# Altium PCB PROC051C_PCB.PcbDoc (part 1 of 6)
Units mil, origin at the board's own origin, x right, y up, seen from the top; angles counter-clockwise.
Board outline 3304.03 x 2647.77 mil, 6 copper layers (TOP, L2, L3, L4, L5, BOTTOM), stack 55.54 mil thick; 370 components, 273 nets, 1273 pads, 1381 vias.
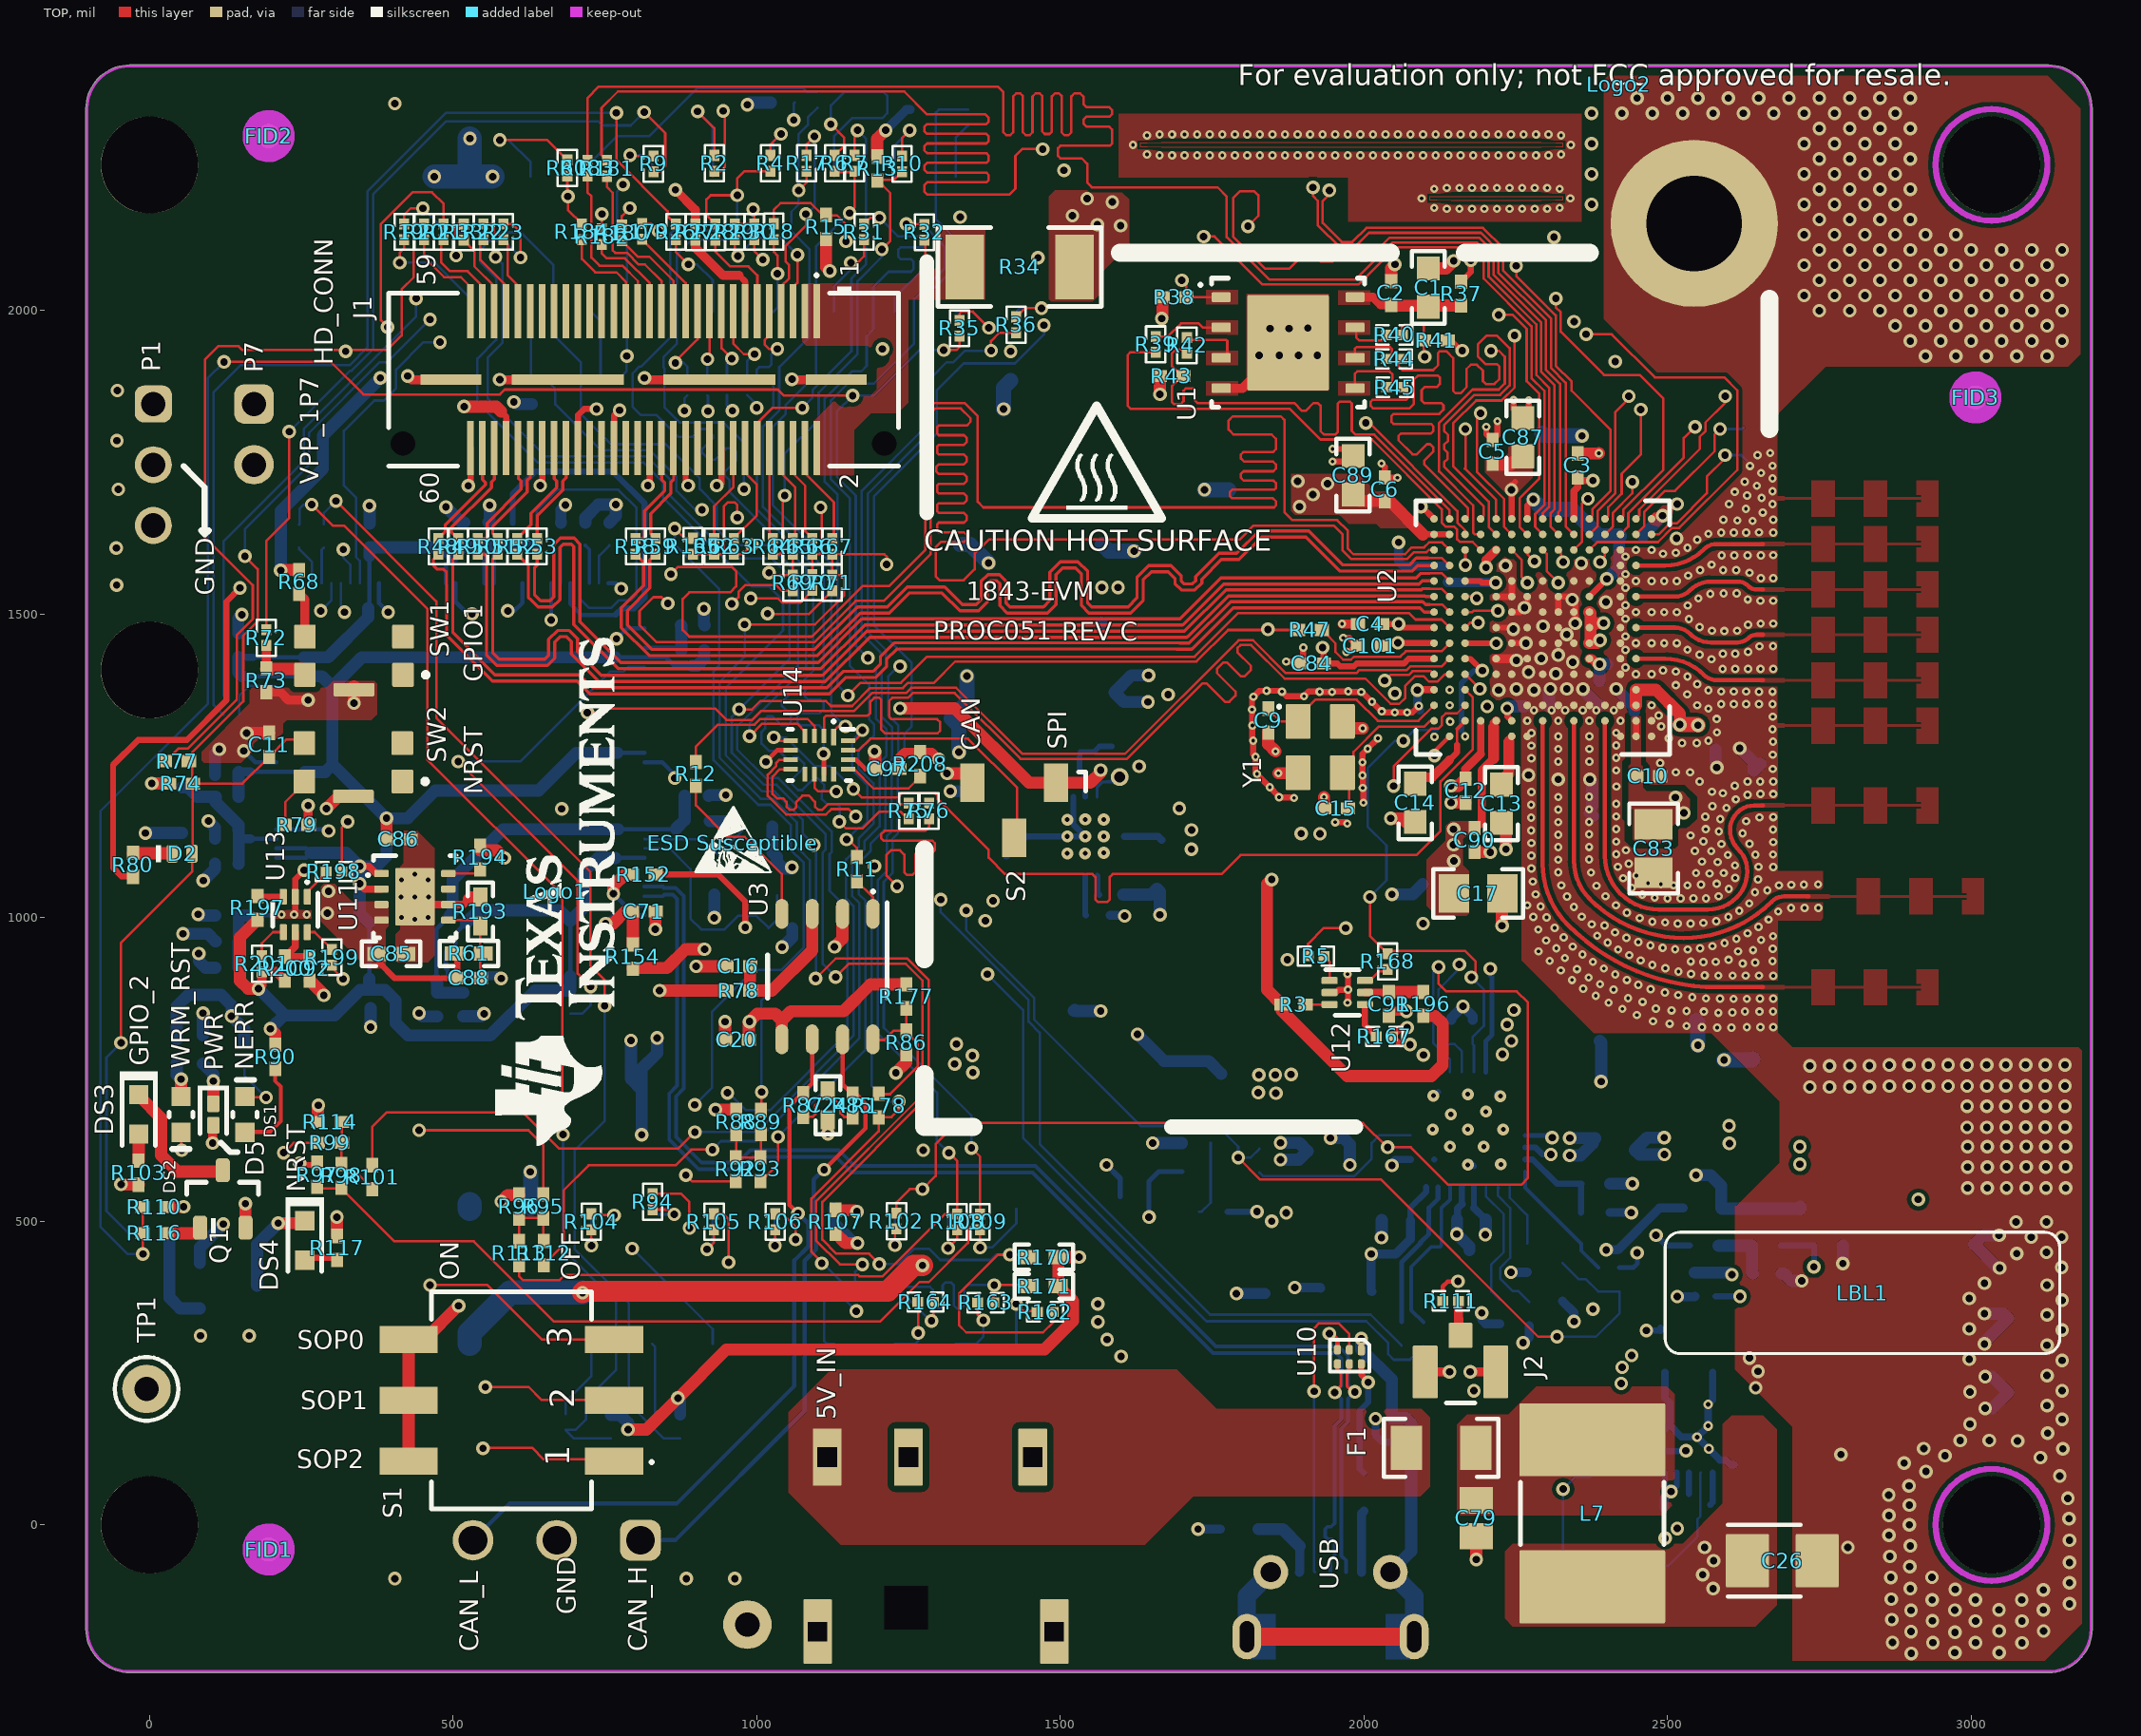
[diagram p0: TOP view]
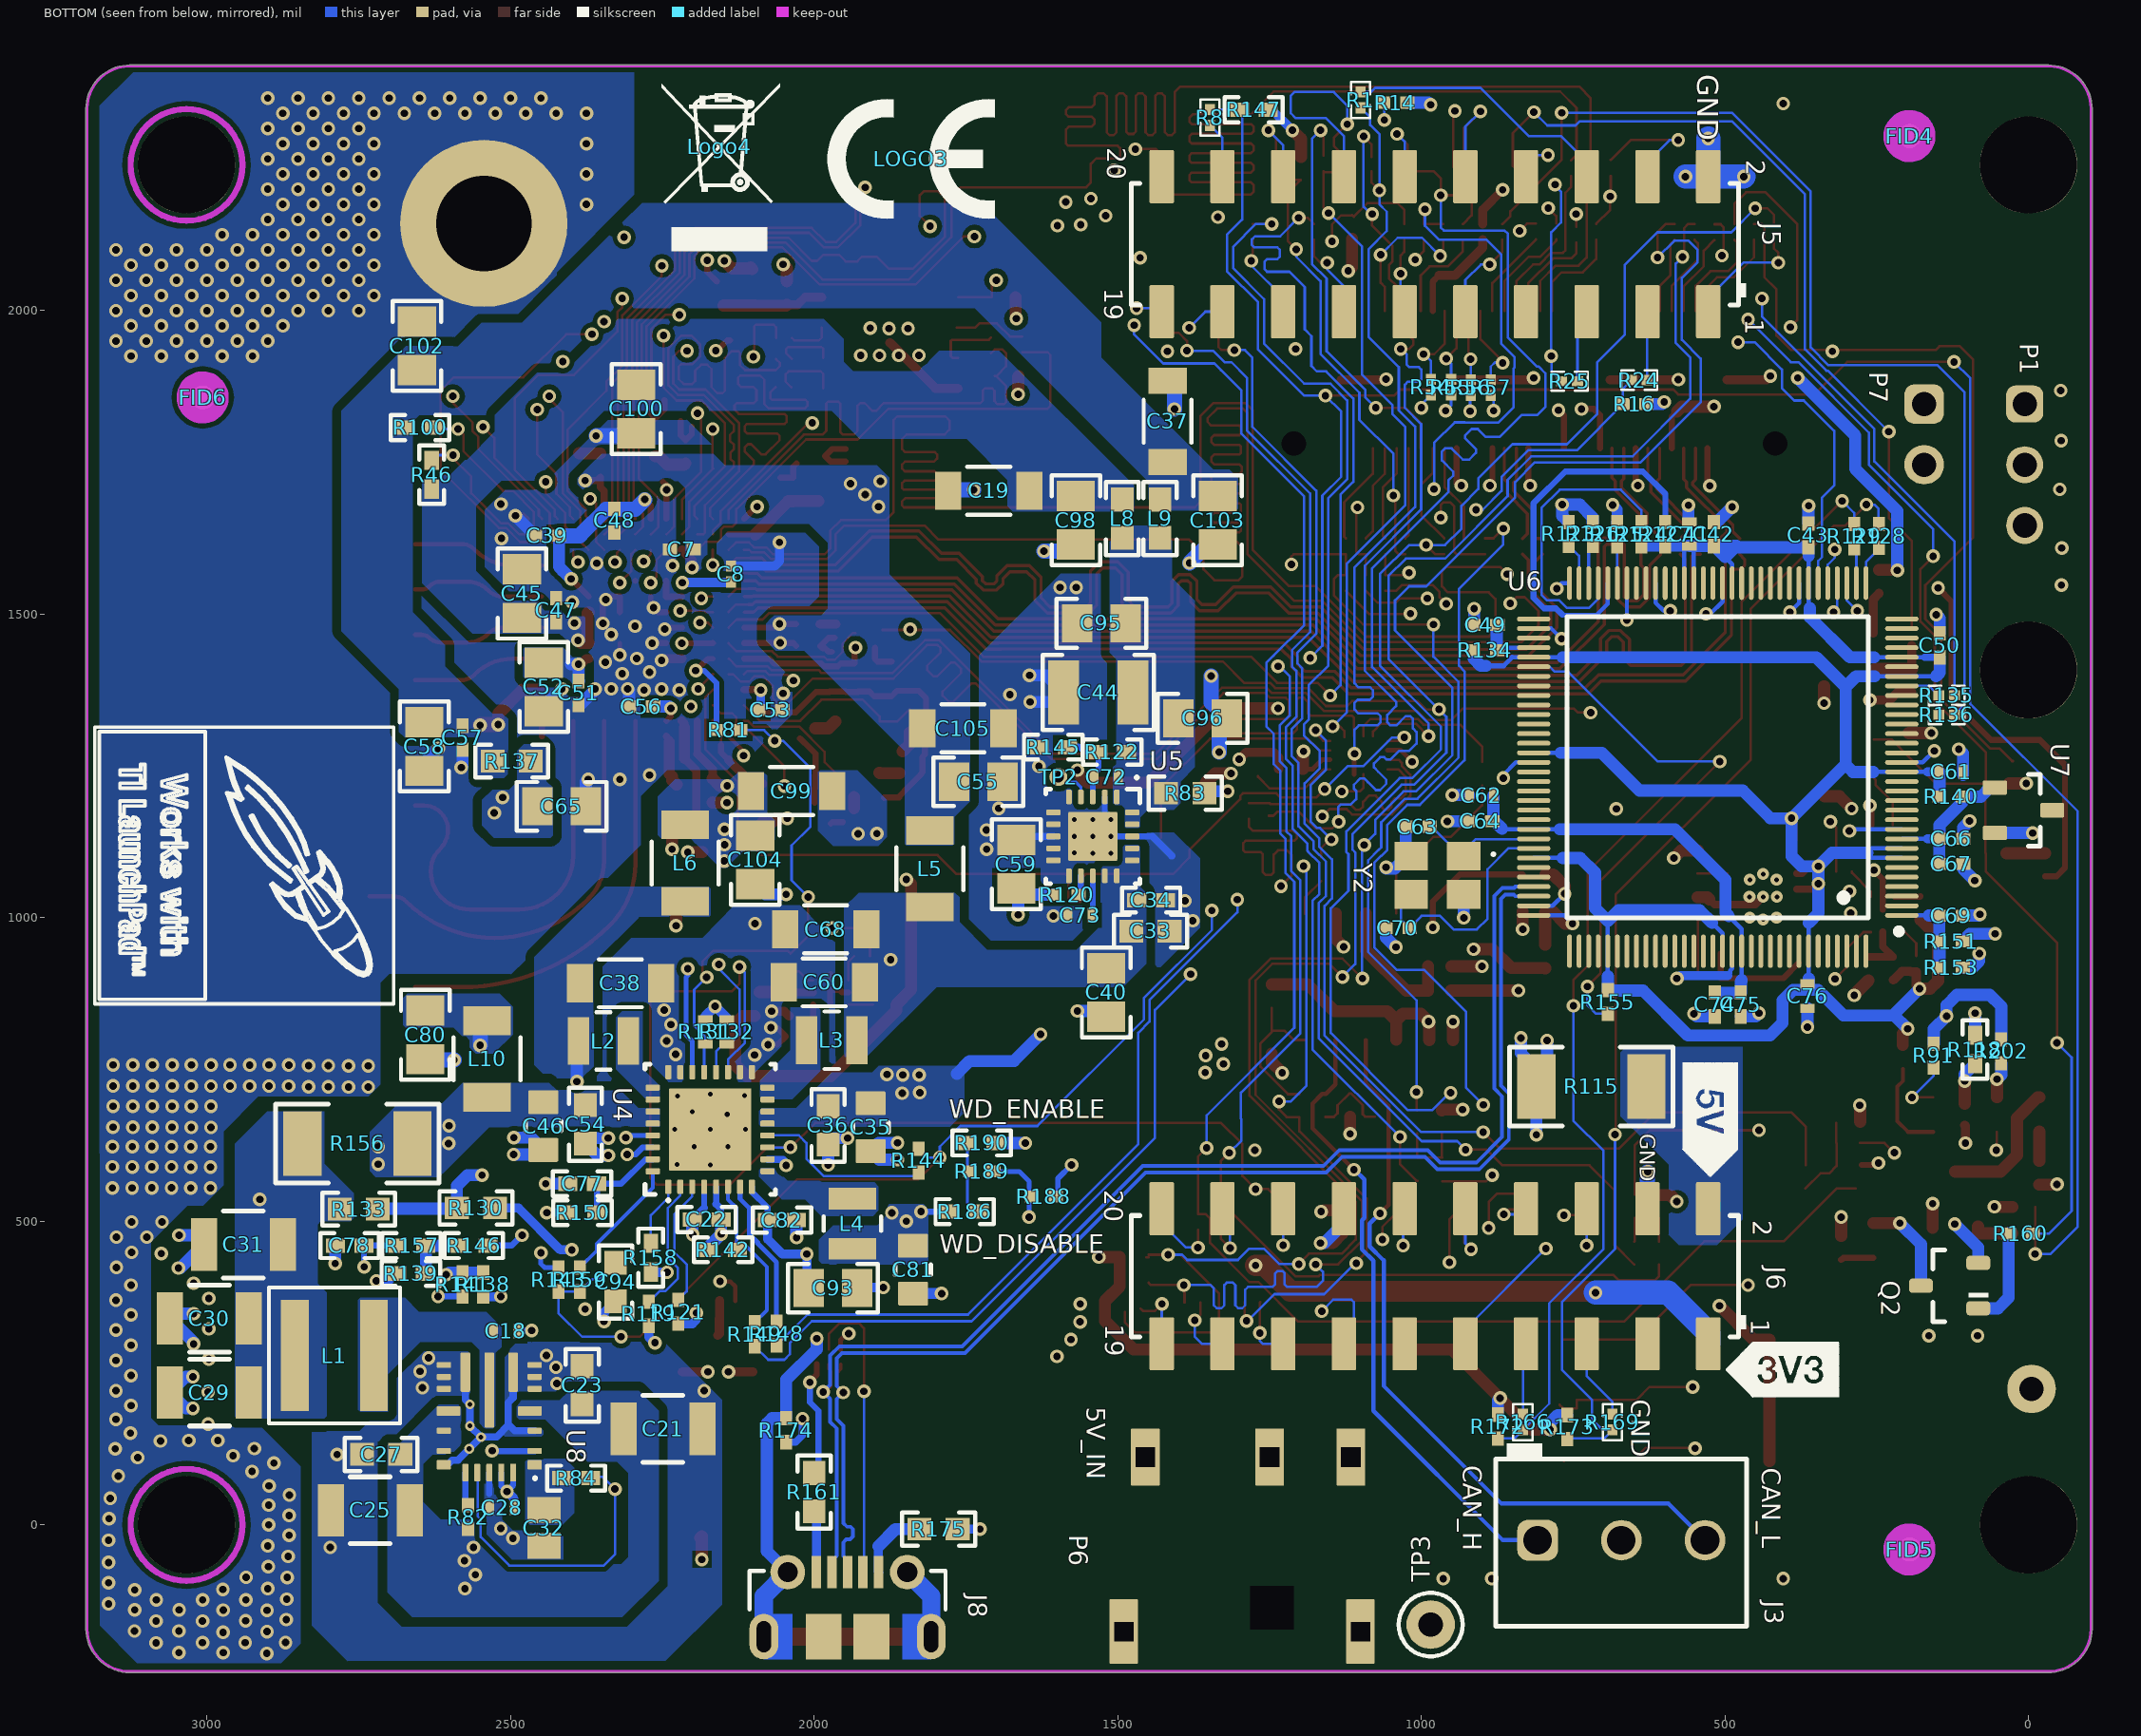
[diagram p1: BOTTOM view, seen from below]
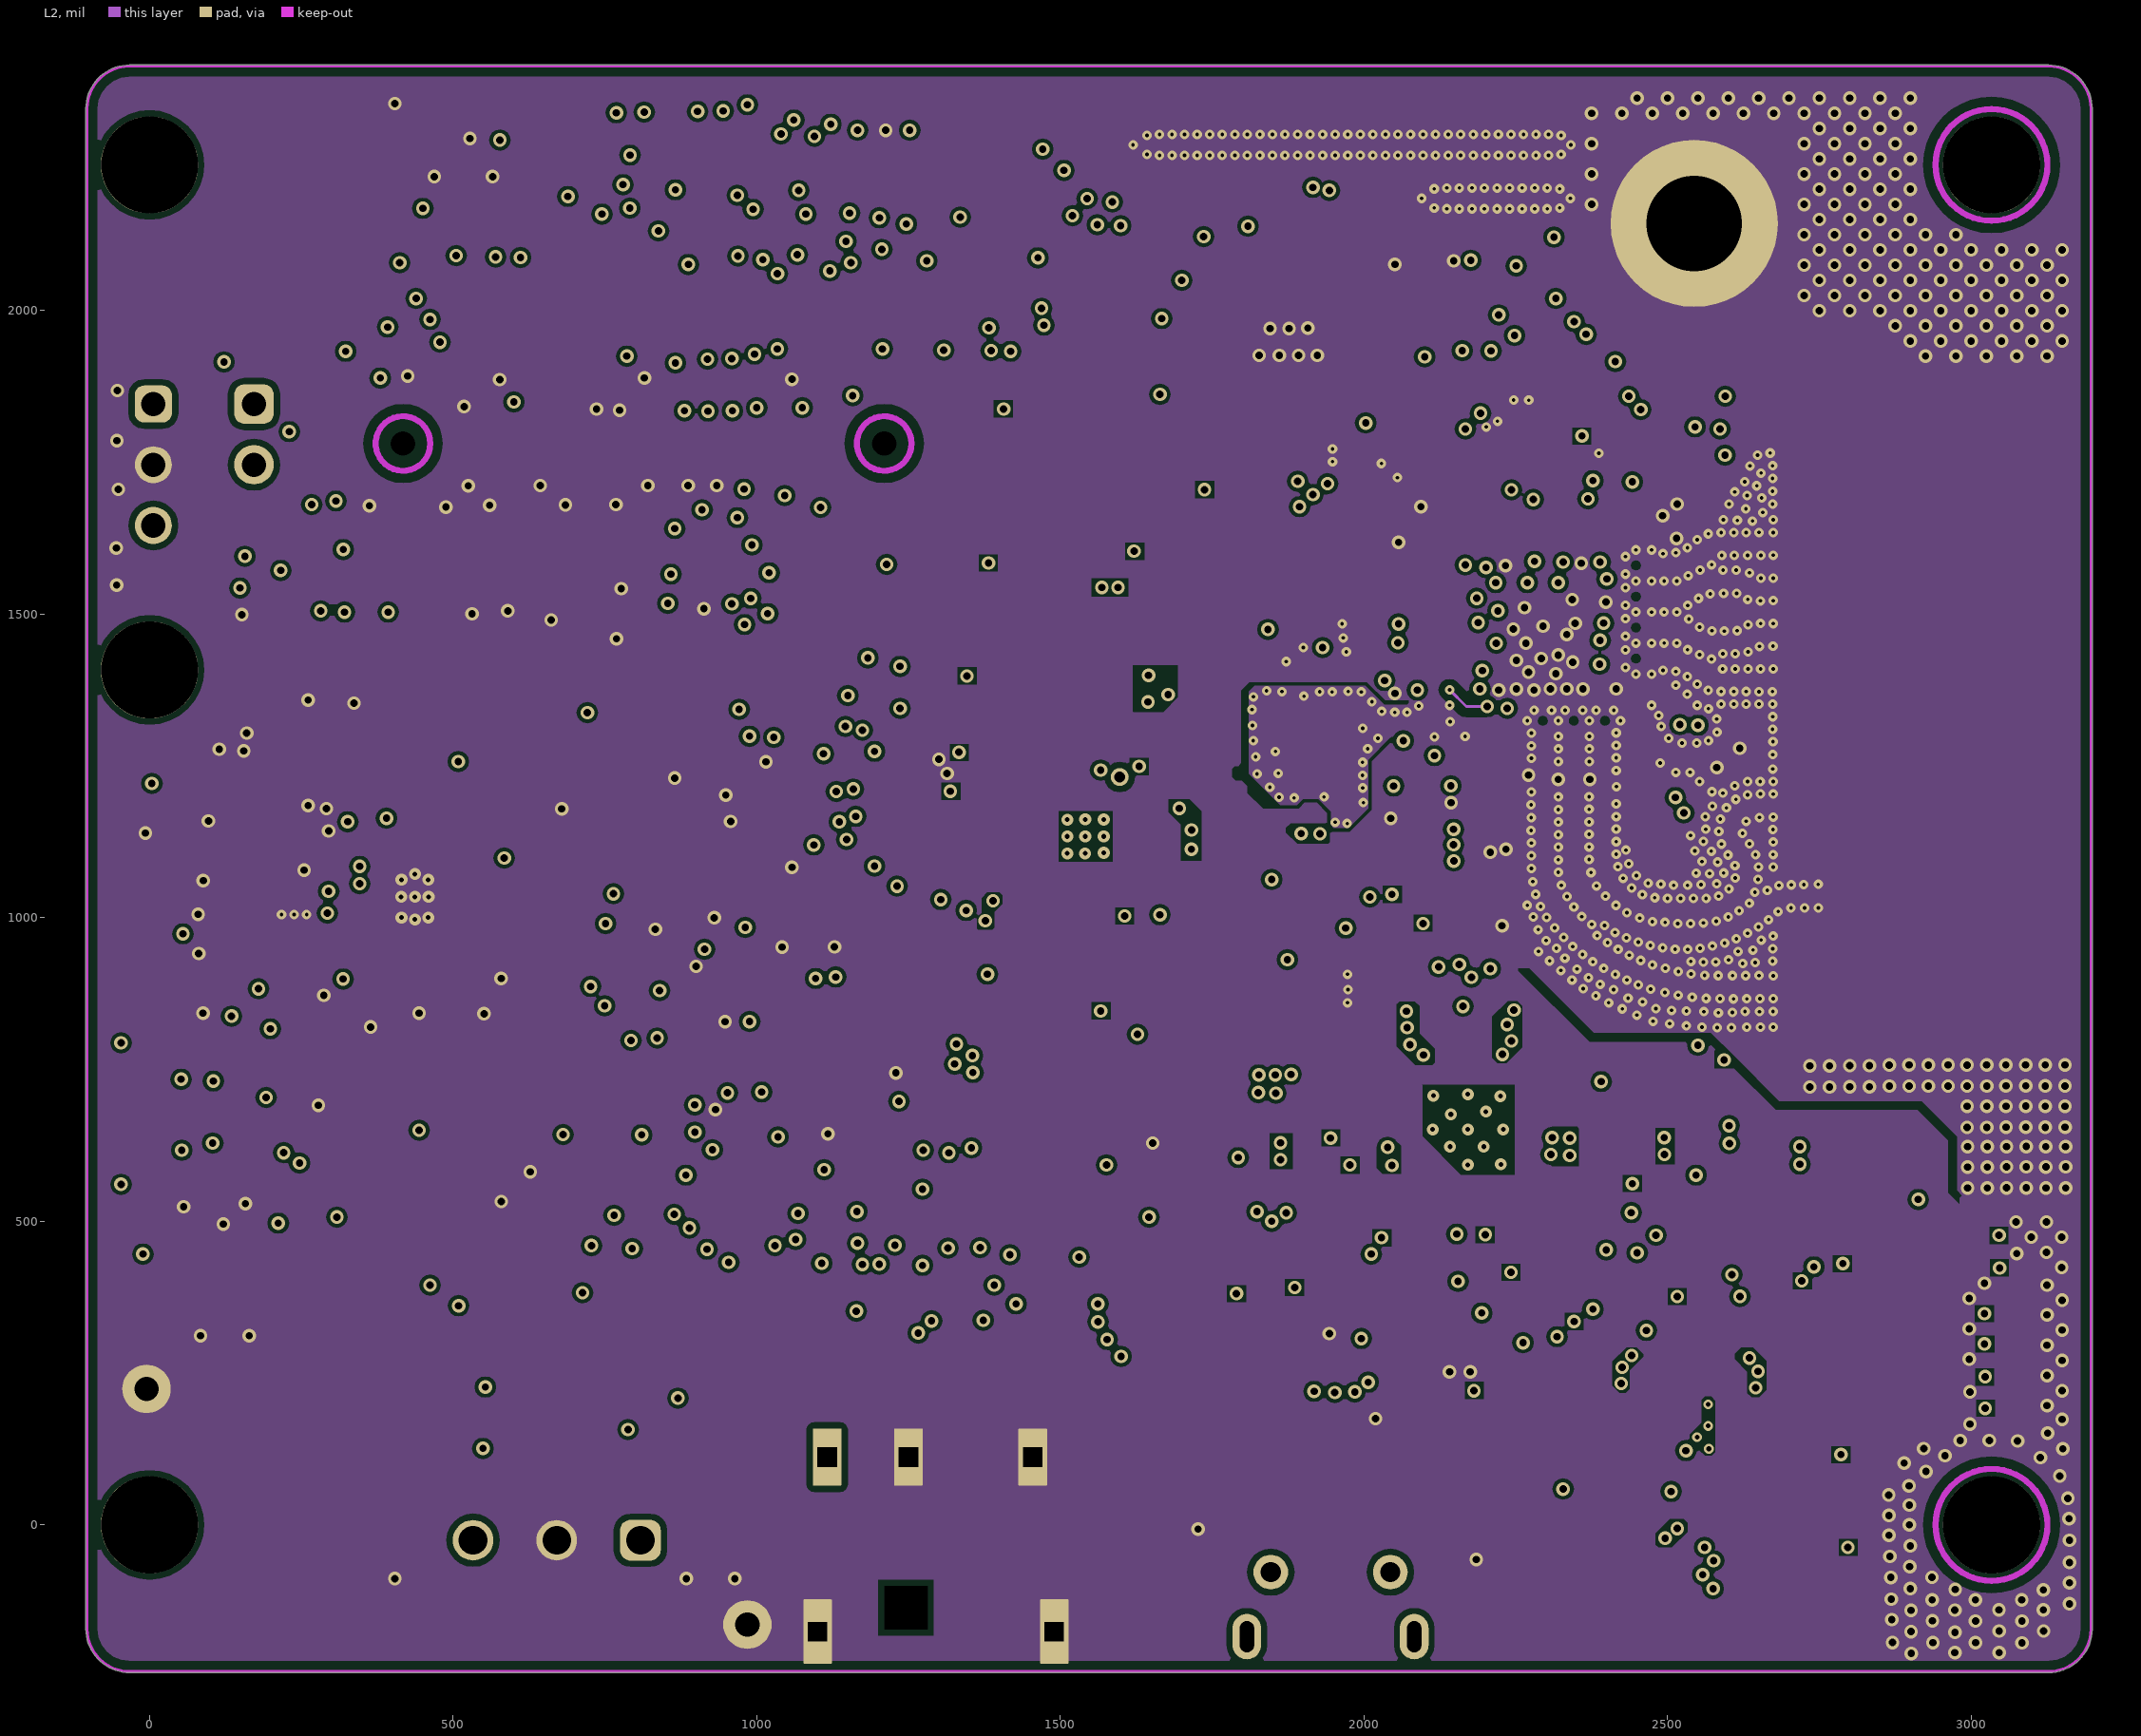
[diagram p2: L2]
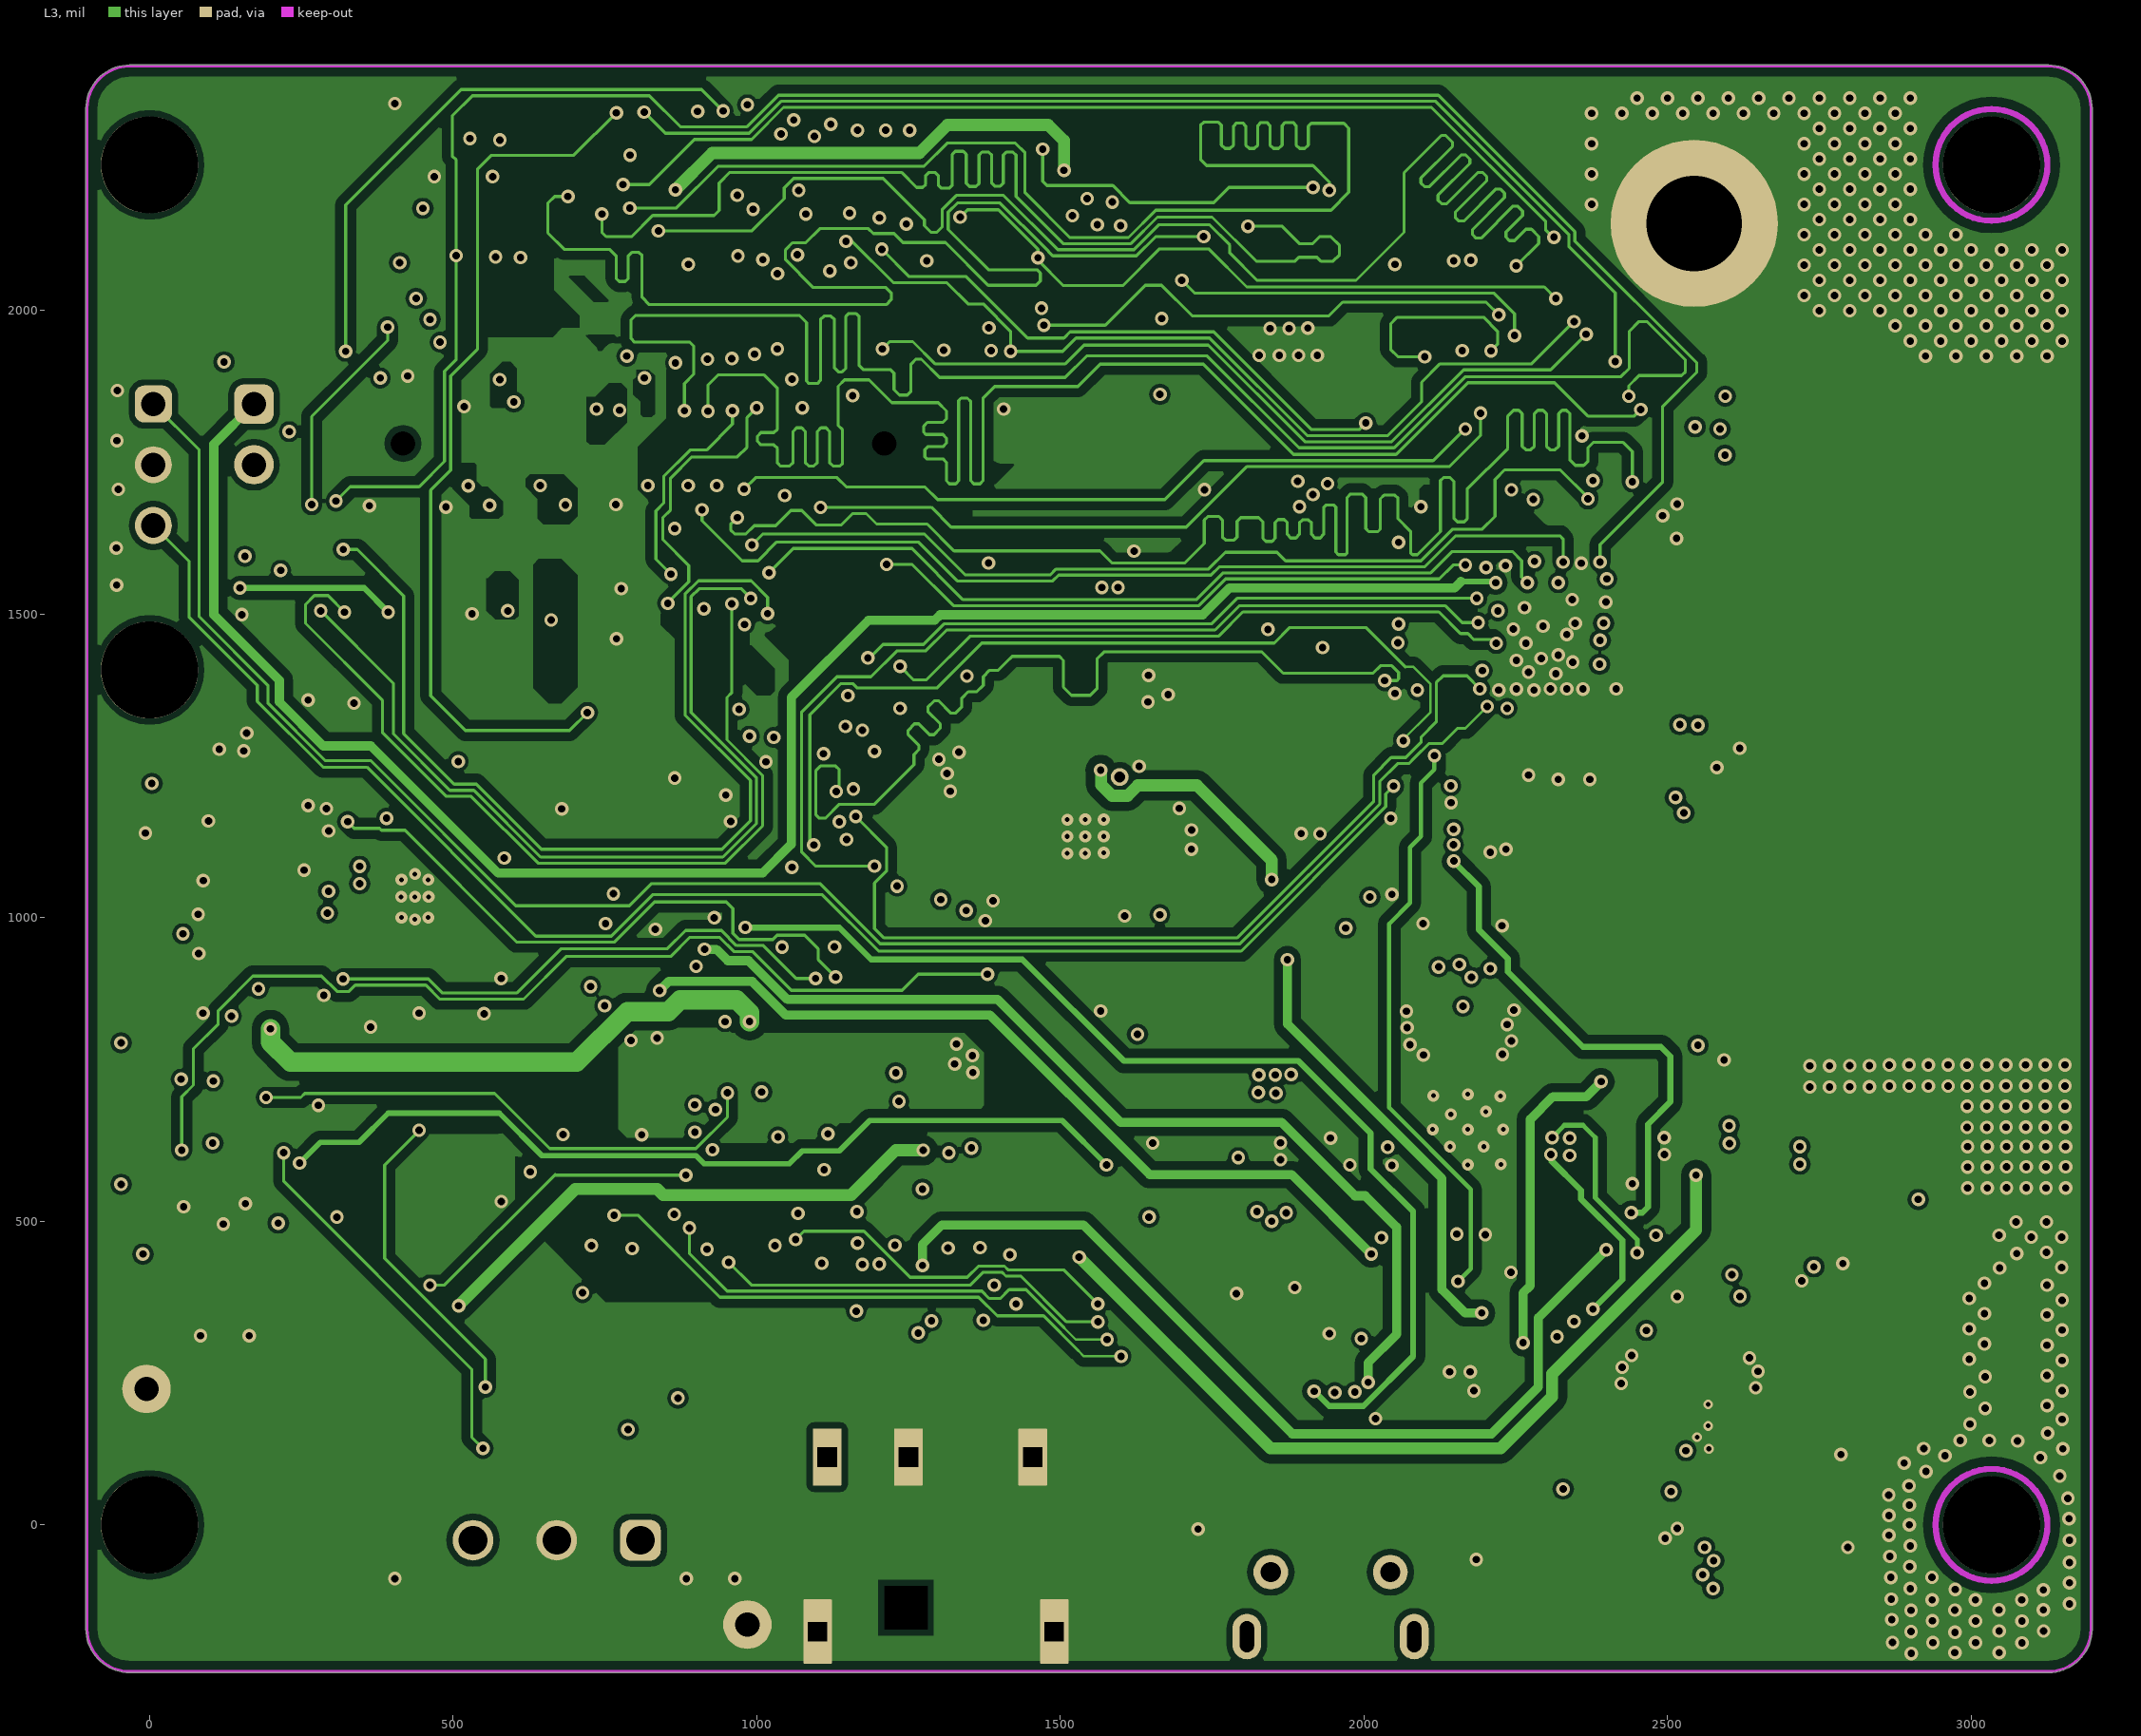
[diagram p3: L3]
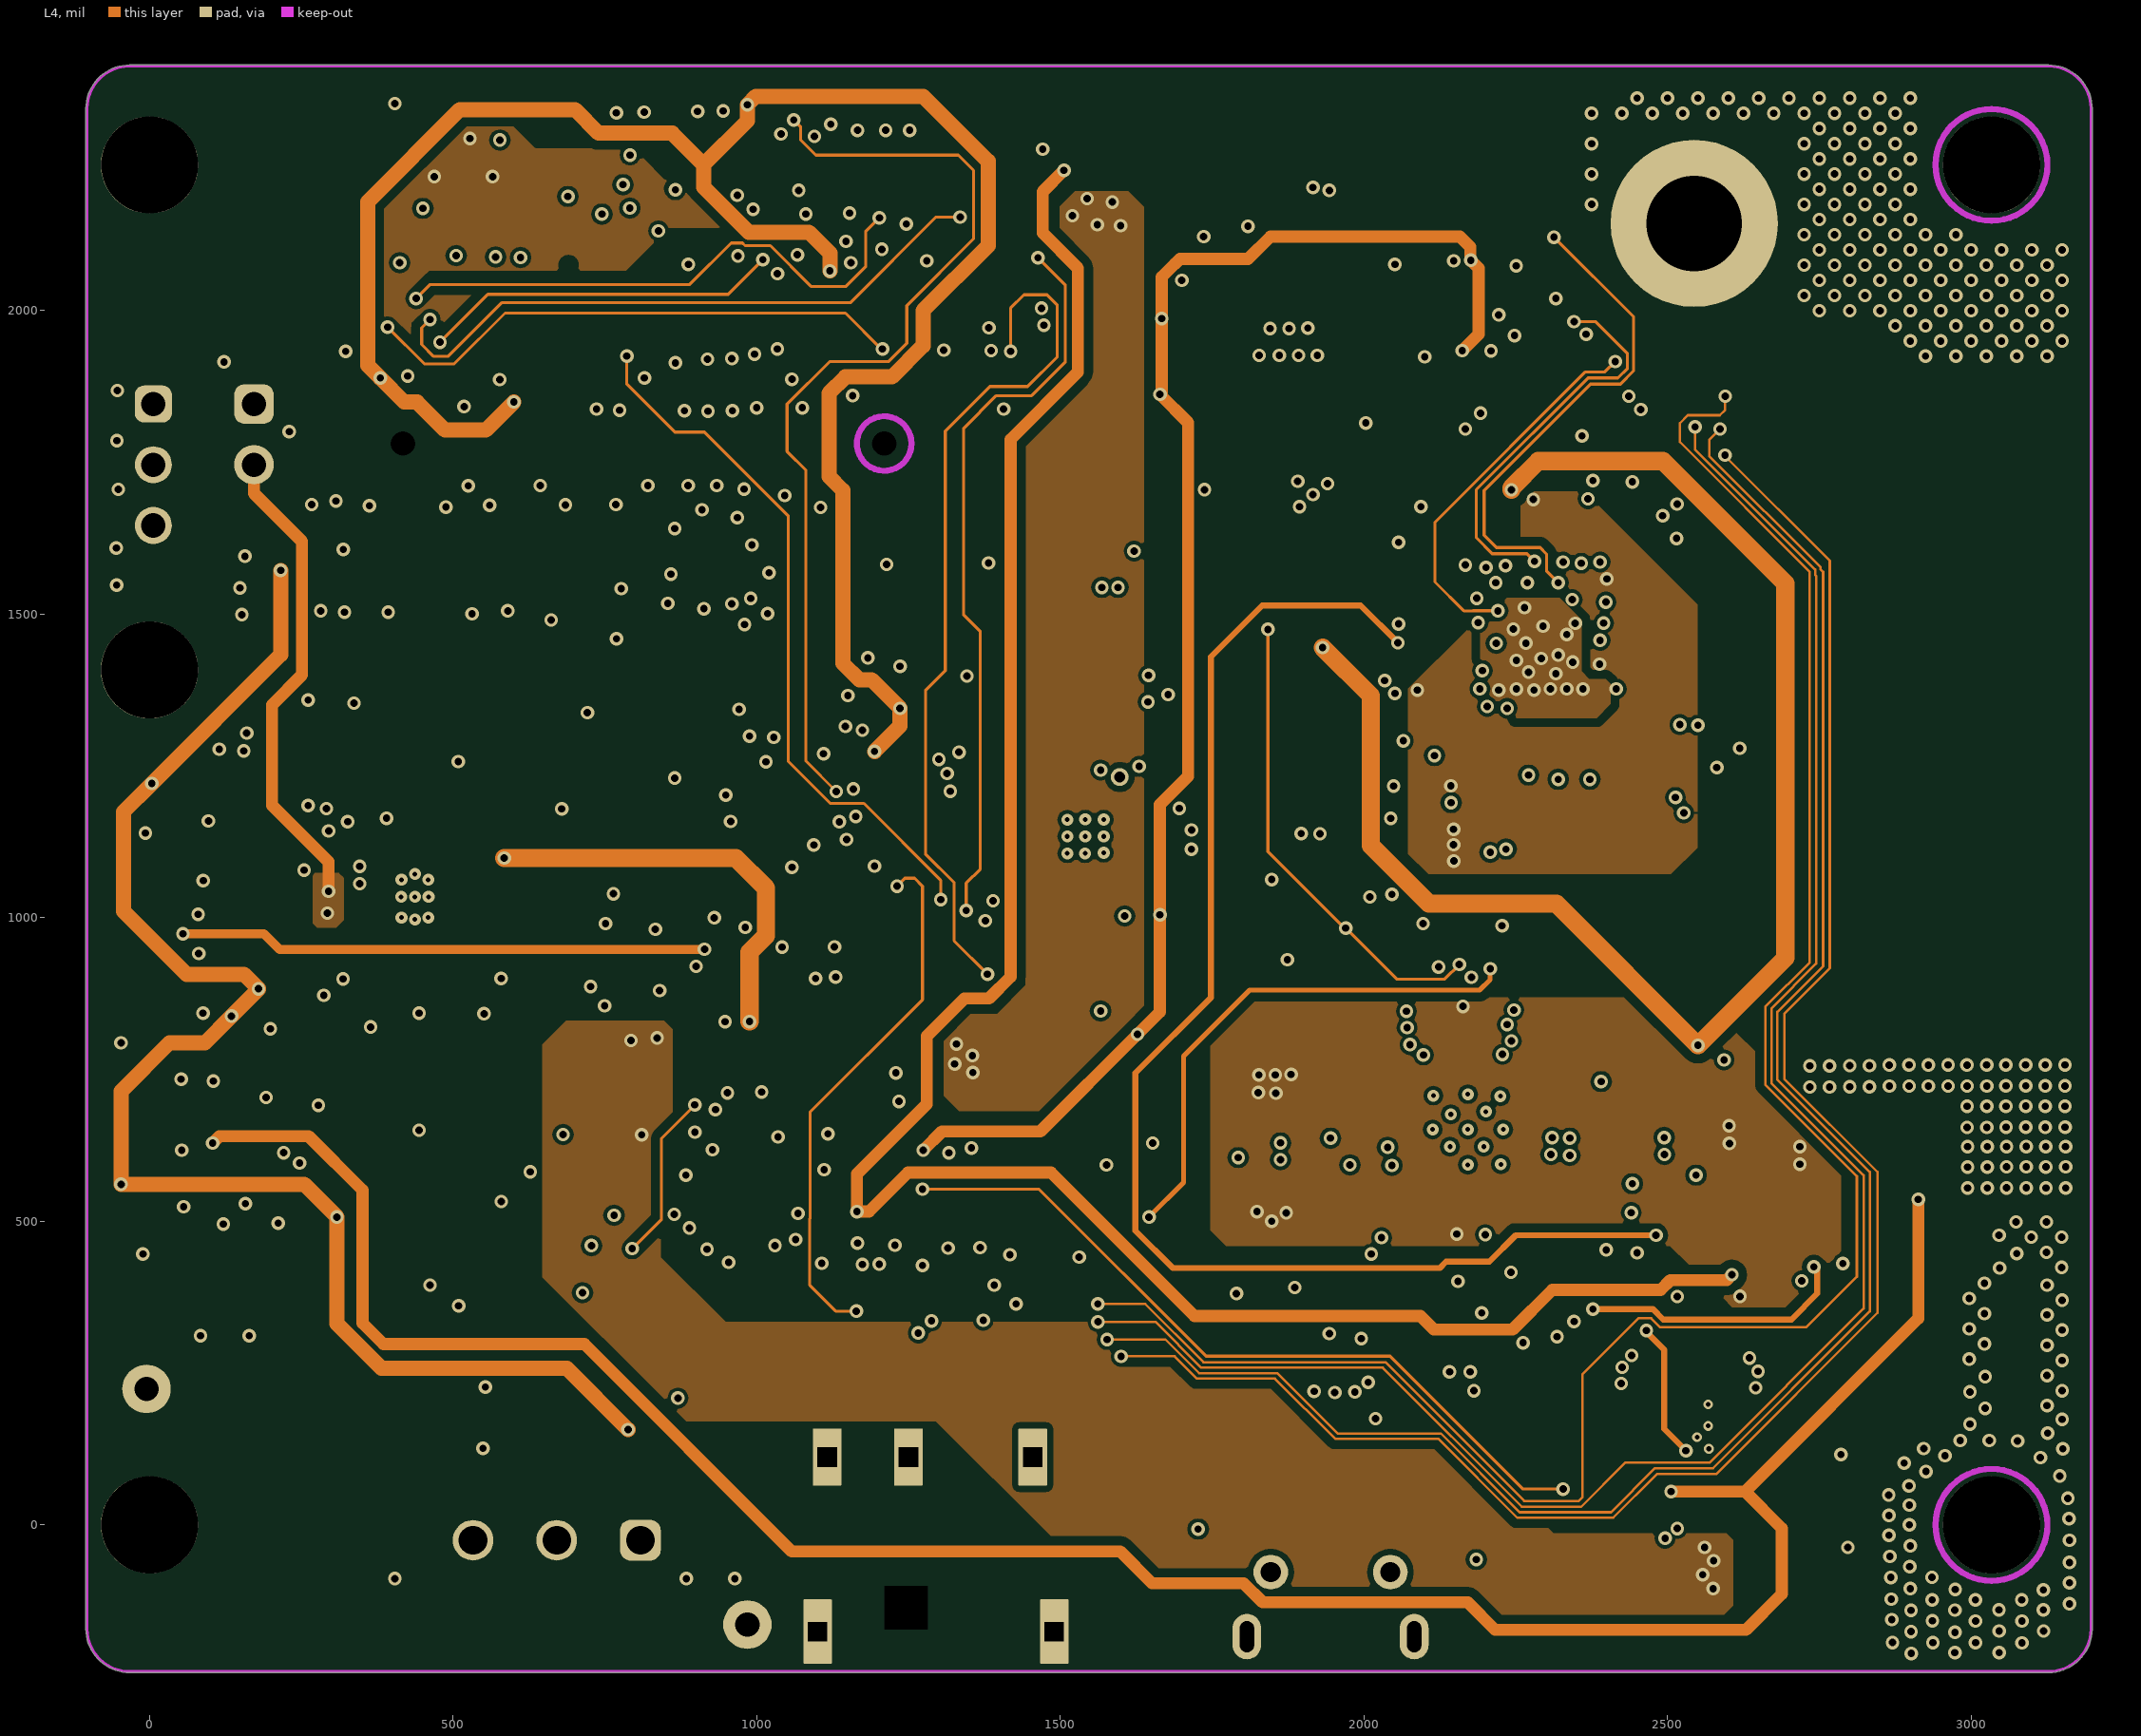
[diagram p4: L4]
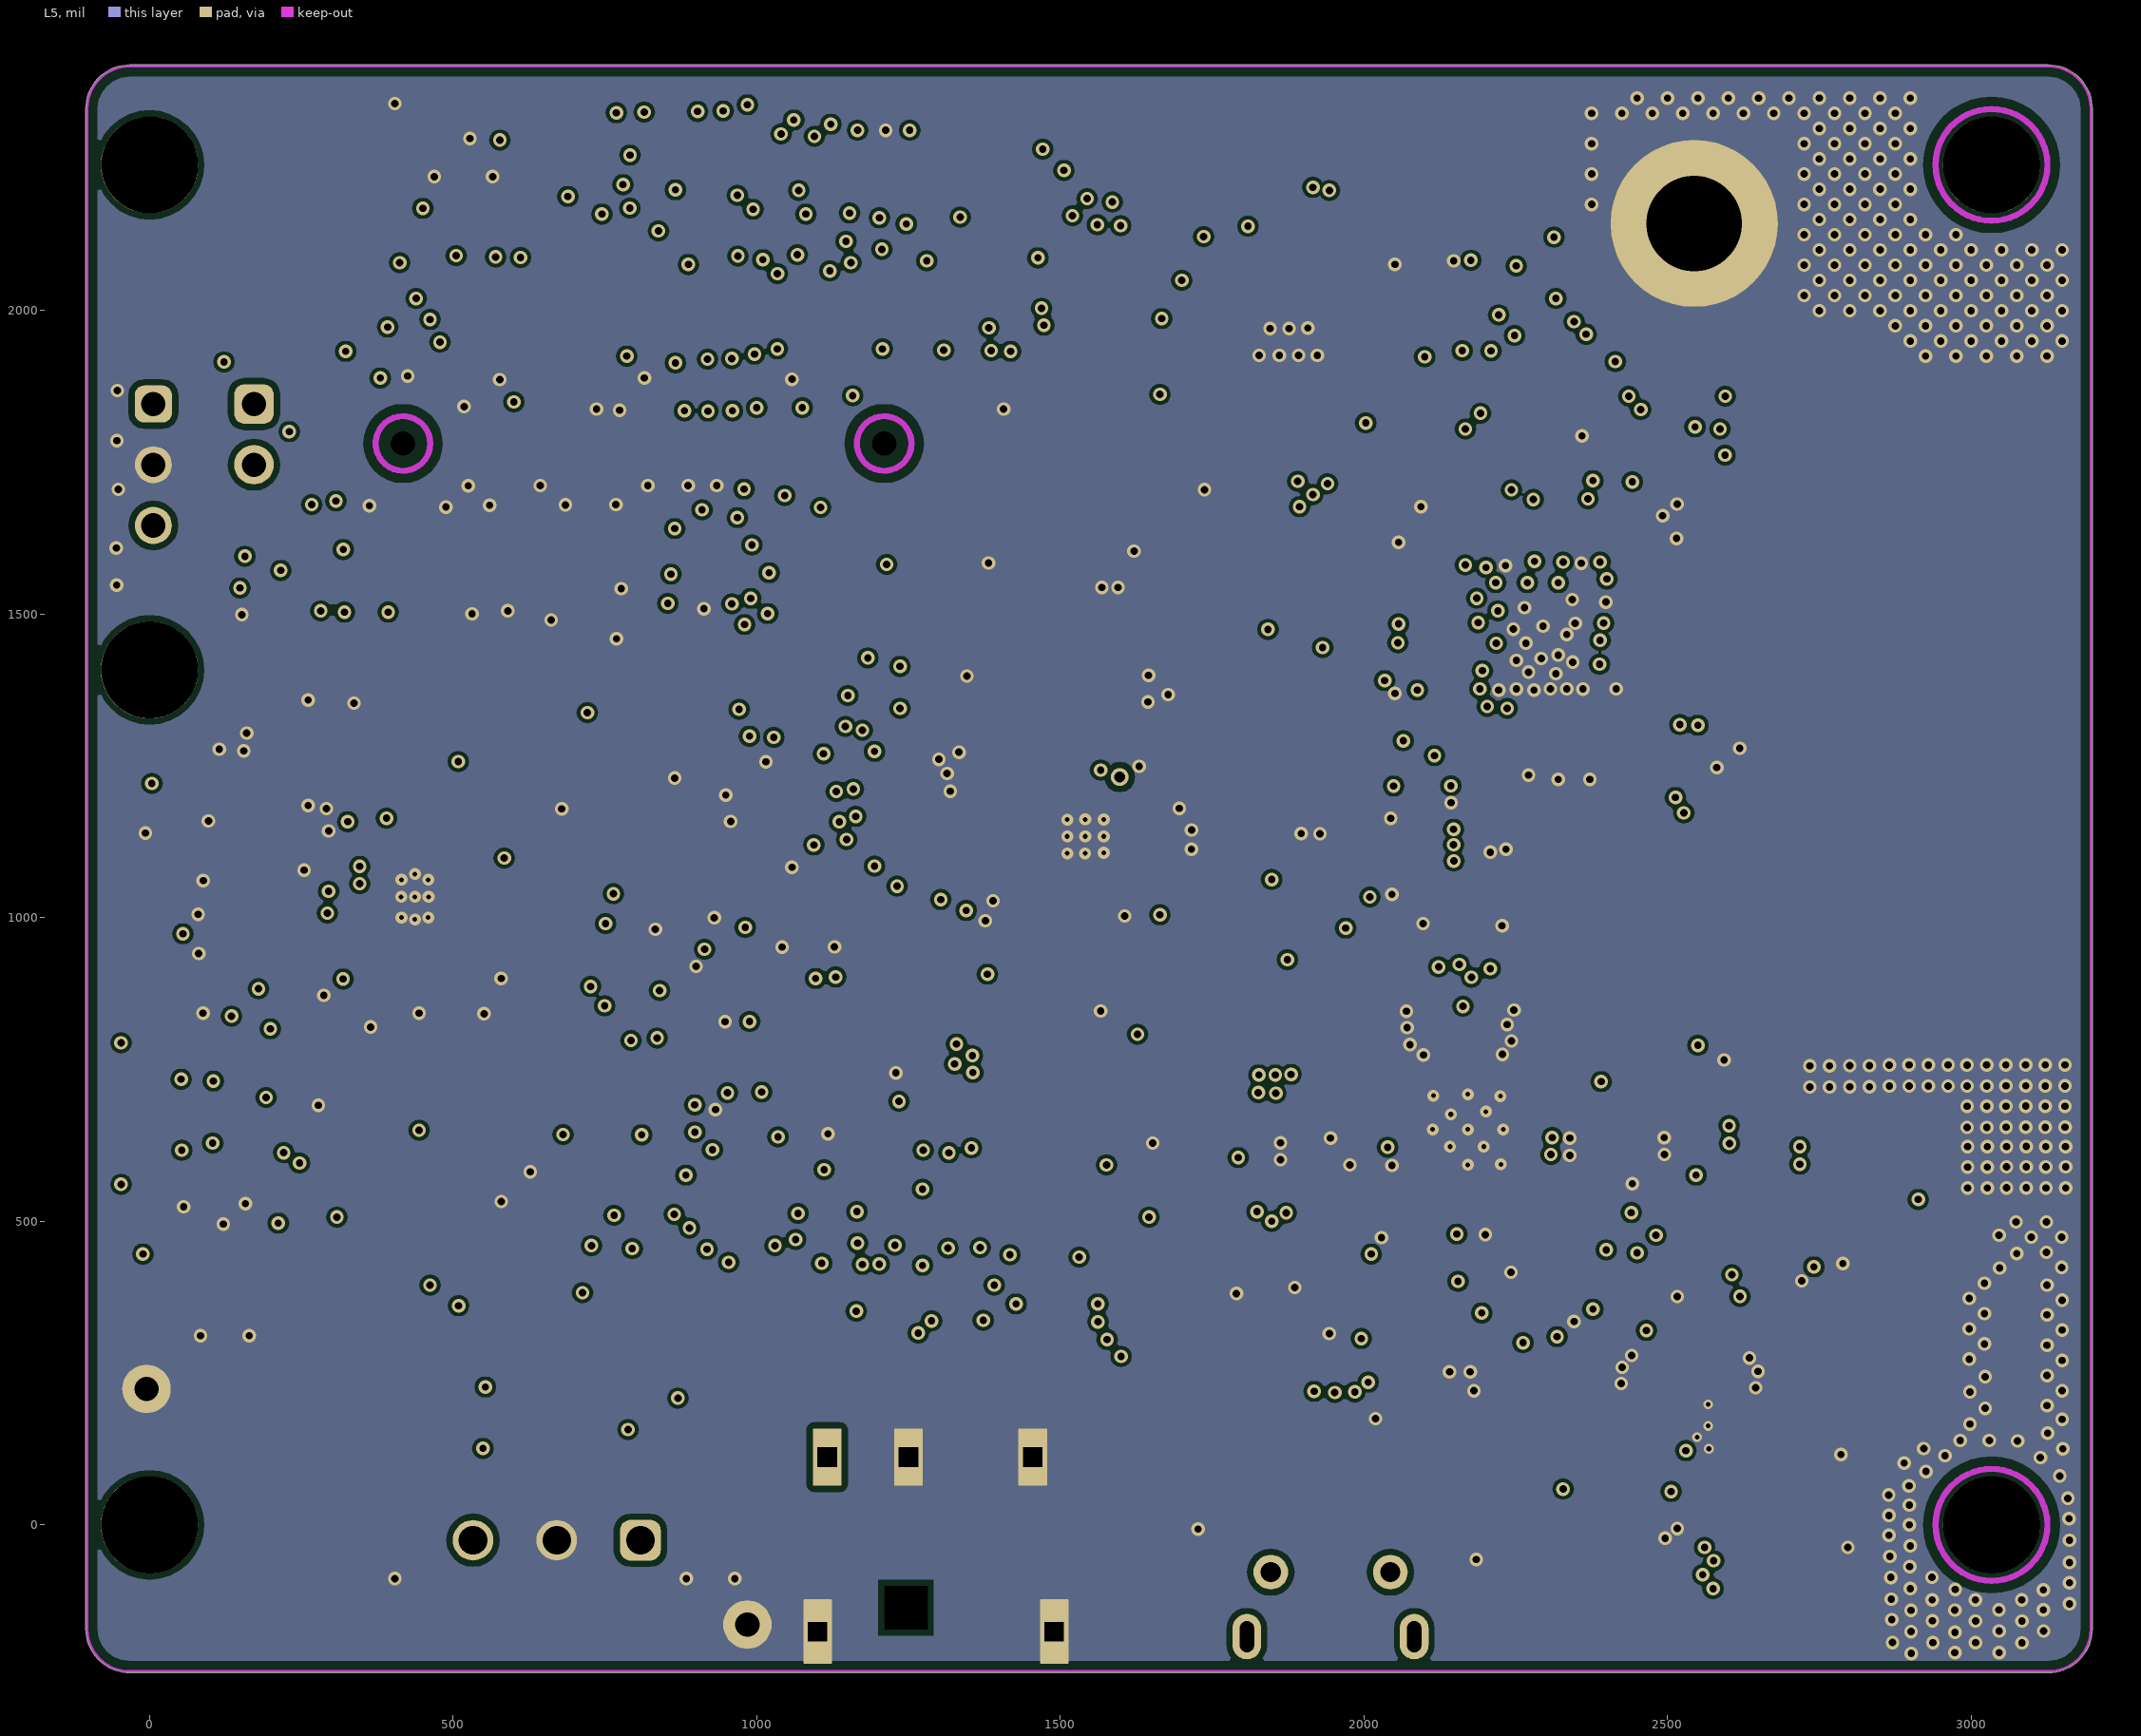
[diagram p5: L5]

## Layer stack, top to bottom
Top Solder: solder mask 0.8, Solder Resist, Dk 3.5
TOP: signal copper 1.6
Dielectric1: core 4, Rogers 4835, Dk 3.66
L2: signal copper 1.2
Dielectric2: prepreg 5.7, 370HR Prepreg 1080, Dk 3.9
L3: signal copper 1.2
Dielectric3: core 28, 370HR Prepreg 1080, Dk 4.36
L4: signal copper 1.2
Dielectric4: prepreg 5.84, 370HR Prepreg 1080, Dk 3.9
L5: signal copper 1.2
Dielectric5: core 4, 370HR Prepreg 1080, Dk 4.26
BOTTOM: signal copper 1.6
Bottom Solder: solder mask 0.8, Solder Resist, Dk 3.5

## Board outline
-104.76,-171.12 cw(c-102.75,-171) -104.76,-171 -104.76,2331.5 cw(c-102.75,2331.5) -104.7,2332 cw(c-102.75,2332.5) -104.76,2332.5 cw(c-32.75,2332.5) -32.75,2404.52 3127.25,2404.52 cw(c3127.25,2332.5) 3199.27,2332.5 3199.27,-172 cw(c3197.25,-172) 3199.26,-172.15 cw(c3127.25,-171.24) 3127.25,-243.26 -32.75,-243.26 cw(c-32.75,-171.24) -104.76,-171.24 cw(c-102.75,-171.24)

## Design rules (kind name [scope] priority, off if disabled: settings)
Clearance Clearance_L34 [InLayerClass('L3_L4')] p1: gap=15 ignorepadtopadclearanceinfootprint=FALSE except(0: Arc-Hole Track-Hole SMDPad-Hole THPad-Hole Via-Hole Fill-Hole Poly-Hole Region-Hole Text-Hole; 5: Arc-Track Arc-SMDPad Track-Track Track-SMDPad; 5.9: Via-Via; 6: Arc-Arc Arc-THPad Arc-Via Track-THPad Track-Via SMDPad-SMDPad SMDPad-THPad SMDPad-Via SMDPad-Fill SMDPad-Poly THPad-THPad THPad-Via Via-Fill Via-Poly; 10: THPad-Fill THPad-Poly)
Clearance Clearance_PMIC [WithinRoom('Copper to PMIC IC')] p2: gap=5 ignorepadtopadclearanceinfootprint=FALSE except(0: Arc-Hole Track-Hole SMDPad-Hole THPad-Hole Via-Hole Fill-Hole Poly-Hole Region-Hole Text-Hole; 4: Arc-Track Track-Track; 4.5: Track-Via SMDPad-SMDPad)
Clearance Clearance_BTM [OnLayer('BOTTOM')] p3: gap=15 ignorepadtopadclearanceinfootprint=FALSE except(0: Arc-SMDPad Arc-Hole Track-Hole SMDPad-Hole THPad-Hole Via-Hole Fill-Hole Poly-Hole Region-Hole Text-Hole; 4: Track-SMDPad; 4.5: Arc-Via Track-Via; 5: Arc-Arc Arc-Track Track-Track SMDPad-Via; 6: Arc-THPad Track-THPad SMDPad-SMDPad SMDPad-THPad THPad-THPad THPad-Via; 8: Arc-Fill Arc-Poly Track-Fill Track-Poly Via-Fill Via-Poly; 9: SMDPad-Fill SMDPad-Poly THPad-Fill THPad-Poly; 16.6: Via-Via)
Clearance Clearance_L25 [InLayerClass('L2_L5')] p4: gap=15 ignorepadtopadclearanceinfootprint=FALSE except(0: Arc-Hole Track-Hole SMDPad-Hole THPad-Hole Via-Hole Fill-Hole Poly-Hole Region-Hole Text-Hole; 5: Arc-Track Arc-SMDPad Track-Track Track-SMDPad; 6: Arc-Arc Arc-THPad Arc-Via Track-THPad Track-Via SMDPad-SMDPad SMDPad-THPad SMDPad-Via SMDPad-Fill SMDPad-Poly THPad-THPad THPad-Via Via-Via Via-Fill Via-Poly; 10: THPad-Fill THPad-Poly)
Clearance RX_TX_L34 [InLayerClass('L3_L4') vs InNetClass('RX_TX')] p5: gap=10 ignorepadtopadclearanceinfootprint=FALSE except(0: Arc-Hole Track-Hole SMDPad-Hole THPad-Hole Via-Hole Fill-Hole Poly-Hole Region-Hole Text-Hole; 4.86: Via-Via; 5: Arc-SMDPad Track-SMDPad; 6: Arc-Arc Arc-Track Arc-THPad Arc-Via Track-Track Track-THPad Track-Via SMDPad-SMDPad SMDPad-THPad SMDPad-Via SMDPad-Fill SMDPad-Poly THPad-THPad THPad-Via Via-Fill Via-Poly; 15: Arc-Fill Arc-Poly Track-Poly Fill-Fill Fill-Poly Poly-Poly; 16: Track-Fill)
Clearance COPLANNER [WithinRoom('COUPLE')] p6: gap=3 ignorepadtopadclearanceinfootprint=FALSE except(0: Arc-Hole Track-Hole SMDPad-Hole THPad-Hole Via-Hole Fill-Hole Poly-Hole Region-Hole Text-Hole)
Clearance Clearance_1 [WithinRoom('DUT') OR InPolygon] p7: gap=6.71 ignorepadtopadclearanceinfootprint=FALSE except(0: Arc-Hole Track-Hole SMDPad-Hole THPad-Hole Via-Hole Fill-Hole Poly-Hole Region-Hole Text-Hole; 4: Track-Track Track-SMDPad Track-Via SMDPad-Via; 6.6: Via-Region; 6.72: Arc-Region Arc-Text Track-Region Track-Text SMDPad-Region SMDPad-Text THPad-Region THPad-Text Via-Text Fill-Region Fill-Text Poly-Region Poly-Text Region-Region Region-Text Text-Text; 9: SMDPad-Poly; 10: THPad-Poly)
Clearance Clearance_TOP [OnLayer('TOP')] p8: gap=10 ignorepadtopadclearanceinfootprint=FALSE except(0: Arc-SMDPad Arc-Hole Track-Hole SMDPad-Hole THPad-Hole Via-Hole Fill-Hole Poly-Hole Region-Hole Text-Hole; 4: Arc-Arc Arc-Track Arc-Via Track-Track Track-SMDPad Track-Via; 5: SMDPad-SMDPad SMDPad-THPad SMDPad-Via; 6: Arc-THPad Track-THPad THPad-THPad THPad-Via Via-Fill Via-Poly; 8: Arc-Fill Arc-Poly Track-Fill Track-Poly; 9: SMDPad-Fill SMDPad-Poly THPad-Fill THPad-Poly; 15: Fill-Fill Fill-Poly Poly-Poly; 15.4: Via-Via)
Clearance RX_TX_L25 [InLayerClass('L2_L5') vs InNetClass('RX_TX')] p9: gap=10 ignorepadtopadclearanceinfootprint=FALSE except(0: Arc-Hole Track-Hole SMDPad-Hole THPad-Hole Via-Hole Fill-Hole Poly-Hole Region-Hole Text-Hole; 5: Arc-SMDPad Track-SMDPad; 6: Arc-Arc Arc-Track Arc-THPad Arc-Via Track-Track Track-THPad Track-Via SMDPad-SMDPad SMDPad-THPad SMDPad-Via SMDPad-Fill SMDPad-Poly THPad-THPad THPad-Via Via-Fill Via-Poly; 9.1: Via-Via; 15: Arc-Fill Arc-Poly Track-Fill Track-Poly Fill-Fill Fill-Poly Poly-Poly)
Clearance RX_TX_TOP [OnLayer('TOP') vs InNetClass('RX_TX')] p10: gap=10 ignorepadtopadclearanceinfootprint=FALSE except(0: Arc-Hole Track-Hole SMDPad-Hole THPad-Hole Via-Hole Fill-Hole Poly-Hole Region-Hole Text-Hole; 4: Arc-Track Arc-SMDPad Track-Track Track-SMDPad SMDPad-Via; 6: Arc-THPad Track-THPad SMDPad-SMDPad SMDPad-THPad THPad-THPad THPad-Via THPad-Fill THPad-Poly; 6.7: Arc-Fill Arc-Poly Track-Fill Track-Poly; 6.72: Arc-Via Track-Via Via-Fill Via-Poly; 9: SMDPad-Fill SMDPad-Poly; 15.4: Via-Via)
Clearance same_net_cl_inner [InLayerClass('layers')] p11: gap=10 ignorepadtopadclearanceinfootprint=FALSE except(0: Arc-Hole Track-Hole SMDPad-Hole THPad-Hole Via-Hole Fill-Hole Poly-Hole Region-Hole Text-Hole; 5: Arc-THPad Track-Track Track-SMDPad Track-THPad SMDPad-SMDPad SMDPad-THPad THPad-THPad; 6: Track-Via SMDPad-Via THPad-Via Via-Via Via-Fill Via-Poly; 15: Arc-Fill Arc-Poly Fill-Fill Fill-Poly Poly-Poly)
DiffPairsRouting Diff_100ohm [InDifferentialPairClass('100_OHM')] p1: maxlimit=5 minlimit=5 mostfreqgap=5 toplayer_minwidth=4 toplayer_maxwidth=5.2 toplayer_prefwidth=5.2 midlayer1_minwidth=4 midlayer1_maxwidth=5.2 midlayer1_prefwidth=5.2 midlayer2_minwidth=4 midlayer2_maxwidth=5.2 midlayer2_prefwidth=5.2 midlayer3_minwidth=4 midlayer3_maxwidth=5.2 midlayer3_prefwidth=5.2 midlayer4_minwidth=4 midlayer4_maxwidth=5.2 midlayer4_prefwidth=5.2 bottomlayer_minwidth=4 bottomlayer_maxwidth=5.2 bottomlayer_prefwidth=5.2 maxuncoupledlength=500
DiffPairsRouting Diff_90ohm [InDifferentialPairClass('90_OHM')] p2: maxlimit=5 minlimit=5 mostfreqgap=5 toplayer_minwidth=5.2 toplayer_maxwidth=5.2 toplayer_prefwidth=5.2 midlayer1_minwidth=6 midlayer1_maxwidth=6 midlayer1_prefwidth=6 midlayer2_minwidth=6 midlayer2_maxwidth=6 midlayer2_prefwidth=6 midlayer3_minwidth=6 midlayer3_maxwidth=6 midlayer3_prefwidth=6 midlayer4_minwidth=6 midlayer4_maxwidth=6 midlayer4_prefwidth=6 bottomlayer_minwidth=6 bottomlayer_maxwidth=6 bottomlayer_prefwidth=6 maxuncoupledlength=500
DiffPairsRouting [All] p3: maxlimit=5 minlimit=4 mostfreqgap=5 toplayer_minwidth=4 toplayer_maxwidth=6 toplayer_prefwidth=5.2 midlayer1_minwidth=4 midlayer1_maxwidth=6 midlayer1_prefwidth=5.2 midlayer2_minwidth=4 midlayer2_maxwidth=6 midlayer2_prefwidth=5.2 midlayer3_minwidth=4 midlayer3_maxwidth=6 midlayer3_prefwidth=5.2 midlayer4_minwidth=4 midlayer4_maxwidth=6 midlayer4_prefwidth=5.2 bottomlayer_minwidth=4 bottomlayer_maxwidth=6 bottomlayer_prefwidth=5.2 maxuncoupledlength=500
HoleSize [All] p1: absolutevalues=TRUE maxlimit=200 minlimit=5.9 maxpercent=80.000 minpercent=20.000
Length DIFF_2 [InDifferentialPairClass('90_OHM')] p1: maxlimit=2250 minlimit=2200
Length DIFF_1 [InDifferentialPairClass('100_OHM')] p2: maxlimit=1910 minlimit=1880
Length QSPI [InxSignalClass('QSPI')] p3: maxlimit=1160 minlimit=950
Length Length_2 [All] p4: maxlimit=20000 minlimit=0
MatchedLengths SPI_2_NEW [InxSignalClass('SPI2')] p1: tolerance=500 checknetsindiffpair=FALSE checkdiffpairvsdiffpair=TRUE checkxsignals=TRUE checkothers=TRUE
MatchedLengths LVDS_1 [InxSignalClass('LVDS')] p2: tolerance=5 checknetsindiffpair=FALSE checkdiffpairvsdiffpair=TRUE checkxsignals=TRUE checkothers=TRUE
MatchedLengths DATA-0-7 [InxSignalClass('DATA_0_7')] p3: tolerance=200 checknetsindiffpair=FALSE checkdiffpairvsdiffpair=TRUE checkxsignals=TRUE checkothers=TRUE
MatchedLengths MUX_TO_J1 [InxSignalClass('mux_to_j1')] p4: tolerance=250 checknetsindiffpair=FALSE checkdiffpairvsdiffpair=TRUE checkxsignals=TRUE checkothers=TRUE
MatchedLengths MUX_J5 [InxSignalClass('mux_to_j5')] p5: tolerance=250 checknetsindiffpair=FALSE checkdiffpairvsdiffpair=TRUE checkxsignals=TRUE checkothers=TRUE
MatchedLengths U2_MUX [InxSignalClass('U2_TO_MUX')] p6: tolerance=250 checknetsindiffpair=FALSE checkdiffpairvsdiffpair=TRUE checkxsignals=TRUE checkothers=TRUE
MinimumAnnularRing [All] p1: minimumring=3.9
MinimumSolderMaskSliver [All] p1: minsoldermaskwidth=4
PlaneConnect [All] p1: planeconnectstyle=Direct reliefexpansion=20 reliefentries=4 reliefconductorwidth=10 reliefairgap=10
PolygonConnect [All] p1: connectstyle=Direct reliefconductorwidth=10 reliefentries=4 polygonreliefangle="90 Angle" airgapwidth=10
RoomDefinition DUT [InComponentClass('DUT')] p1: confinementstyle=ConfineIn formatcopy=TRUE lockcomponents=FALSE outline 2143,1735.5 2154,1746.5 3074,1746.5 3100,1720.5 3100,619.5 3078,597.5 2381,597.5 2306,672.5 2306,1214.5 2269,1251.5 2156,1251.5 2093,1314.5 2093,1712.5 2116,1735.5
RoomDefinition COUPLE [WithinRoom('CO_PLANNER')] p2: confinementstyle=ConfineOut formatcopy=TRUE lockcomponents=FALSE outline 1592.53,2331.66 1593.27,2330.92 2361.57,2330.92 2361.57,2143.54 2358.68,2140.65 1974.97,2140.65 1965.68,2149.94 1965.68,2214.31 1595.03,2214.31 1586.93,2222.41
RoutingVias [All] p1: holewidth=12.2 width=22.4 viastyle="Through Hole" minholewidth=5.9 minwidth=13 maxholewidth=24 maxwidth=50
SilkToBoardRegionClearance [Not ((IsComment or IsDesignator) And (Hide <> 'False')) and not InRegion(1000,500,4000,800)] p1:
SilkToSilkClearance [All] p1: silktosilkclearance=3
SilkToSolderMaskClearance SilkscreenOverComponentPads [IsPad] p1: minsilkscreentomaskgap=3 clearancetoexposedcopper=TRUE
SolderMaskExpansion [All] p1: expansion=0
ViasUnderSMD [All] p1: allowed=FALSE
Width Width_1 [All] p1: maxlimit=100 minlimit=4 preferedwidth=10 minimp=50.000000 maximp=50.000000 favimp=50.000000
Width Width_pmic [WithinRoom('PMIC')] p2: maxlimit=100 minlimit=4 preferedwidth=5 toplayer_prefwidth=4 midlayer1_minwidth=5 midlayer2_minwidth=5 midlayer3_minwidth=5 midlayer4_minwidth=5 bottomlayer_prefwidth=4 minimp=50.000000 maximp=50.000000 favimp=50.000000
Width Width_100 [InDifferentialPairClass('DIIF')] p3: maxlimit=5.2 minlimit=5 preferedwidth=5 toplayer_minwidth=5.2 toplayer_prefwidth=5.2 midlayer1_maxwidth=5 midlayer2_maxwidth=5 midlayer3_maxwidth=5 midlayer4_maxwidth=5 bottomlayer_maxwidth=5 minimp=50.000000 maximp=50.000000 favimp=50.000000
Width Width_50ohm [InNetClass('50_OHM')] p4: maxlimit=11 minlimit=9 preferedwidth=9 toplayer_minwidth=11 toplayer_prefwidth=11 midlayer1_minwidth=0 midlayer1_maxwidth=0 midlayer1_prefwidth=0 midlayer2_maxwidth=9 midlayer3_maxwidth=9 midlayer4_minwidth=0 midlayer4_maxwidth=0 midlayer4_prefwidth=0 bottomlayer_maxwidth=9 minimp=50.000000 maximp=50.000000 favimp=50.000000
Width Width_PWR [InNetClass('PWR')] p5: maxlimit=100 minlimit=6 preferedwidth=25
Width Width_room1 [All] p6: maxlimit=100 minlimit=10 preferedwidth=20
23 further rules are at their usual default settings.

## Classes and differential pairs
net class USB: XDSET_1_D_N XDSET_1_D_P
net class Undefined: AR_LVDS_0_N AR_LVDS_0_P AR_LVDS_1_N AR_LVDS_1_P AR_LVDS_CLK_N AR_LVDS_CLK_P AR_LVDS_FRCLK_N AR_LVDS_FRCLK_P NetJ1_26 NetJ1_28 NetJ1_44 NetJ1_46 NetJ1_50 NetJ1_52 NetJ1_56 NetJ1_58 VCC_LDO_OUT
net class QSPI: AR_QSPI_CS AR_QSPI_D0 AR_QSPI_D1 AR_QSPI_D2 AR_QSPI_D3 AR_QSPI_SCLK NetR39_2 NetR40_1 NetR42_2 NetR44_1 NetR45_1
net class PWR: 1V8 1V24 3V3 5VBST +3.3VD AR_1P0_RF1 AR_1P0_RF2 AR_1V4_APLL AR_1V4_SYNTH AR_1V8 AR_1V24 AR_3V3 AR_VBGAP AR_VOUT_PA GND MCU_3V3 MCU_5V NetC1_2 NetC16_2 NetC79_1 NetC85_1 NetJ1_1 NetR3_1 NetR86_1 NetR197_1 VBUS_1_DETECT VDDC_1 VIN VPP_1P7
component class "PROC051C_XDS110 Interface_1B": C49 C63 C66 C67 C70 C71 R123 R124 R125 R126 R127 R128 R129 R134 R135 R136 R140 R152 R154 R155 U6 U7 Y2
component class "PROC051C_XDS110 Interface_1A": C41 C42 C43 C50 C61 C62 C64 C69 C74 C75 C76 J8 R151 R153 R161 R174 R175 U10
component class PROC051C_VPP_Supply: C85 C86 C88 P7 R61 R193 R194 U11
component class PROC051C_Tempsensor: C91 C92 R3 R5 R167 R168 R196 R197 R198 R199 R200 R201 U12 U13
component class PROC051C_SOP_Headers_Reference: R88 R89 R92 R93 R95 R96 R97 R98 R99 R101 R112 R113 R114 S1
component class PROC051C_RST_LEDs: C11 D2 DS1 DS2 DS3 DS4 Q1 Q2 R68 R72 R73 R74 R77 R79 R80 R90 R103 R110 R116 R117 R130 R133 R160 R202 SW1 SW2
component class PROC051C_QSPI_Flash_Reference: C1 C2 R37 R38 R39 R40 R41 R42 R43 R44 R45 U1
component class PROC051C_PWR_In_Reference: C18 C21 C22 C23 C25 C26 C27 C28 C29 C30 C31 C32 C33 C34 C35 C36 C38 C40 C44 C46 C54 C59 C60 C68 C72 C73 C77 C78 C79 C81 C82 C93 C94 C95 C96 D5 F1 L1 L2 L3 L4 L7 P6 R82 R83 R84 R118 R119 R120 R121 R122 R131 R132 R138 R139 R141 R142 R143 R144 R145 R146 R147 R148 R149 R150 R156 R157 R158 R159 R186 R188 R189 R190 TP1 TP2 TP3 U4 U5 U8
component class "PROC051C_LP Connector": J5 J6 P1 R1 R2 R4 R6 R8 R9 R10 R18 R19 R24 R25 R26 R31 R32 R35 R36 R60 R76 R94 R102 R104 R105 R106 R107 R108 R109 R115 R162 R163 R164 R165 R166 R169 R172 R173
component class PROC051C_LC_Filtering_Reference: C19 C37 C55 C80 C98 C99 C100 C102 C103 C104 C105 L5 L6 L8 L9 L10 R137
component class "PROC051C_HD Connector": J1 J2 R7 R17 R20 R21 R22 R23 R27 R28 R29 R30 R33 R34 R48 R49 R50 R51 R52 R53 R54 R55 R56 R57 R58 R59 R62 R63 R64 R65 R66 R67 R69 R70 R71 R75 R111 R179 R180 R181 R182 R183 R184
component class PROC051C_DUT_Reference: C8 C9 C15 R13 R14 R15 R16 R46 R47 R81 R91 R100 R170 R171 U2 Y1
component class PROC051C_Decoupling_Caps_Reference: C3 C4 C5 C6 C7 C10 C12 C13 C14 C17 C39 C45 C47 C48 C51 C52 C53 C56 C57 C58 C65 C83 C84 C87 C89 C90 C101
component class PROC051C_CAN_Interface: C16 C20 C24 C97 J3 R11 R12 R78 R85 R86 R87 R177 R178 R208 S2 U3 U14
component class Header: P1 P7
component class Label: LBL1
component class AssemblyNote: ZZ1 ZZ2 ZZ3 ZZ4 ZZ5
component class FiducialMark: FID1 FID2 FID3 FID4 FID5 FID6
component class PROC051C_Hardware: "CAUTION HOT SURFACE" "ESD Susceptible" FID1 FID2 FID3 FID4 FID5 FID6 LBL1 Logo1 Logo2 LOGO3 Logo4 ZZ1 ZZ2 ZZ3 ZZ4 ZZ5
component class Logo: Logo1
differential pair class 100_OHM: AR_LVDS_0 AR_LVDS_1 AR_LVDS_CLK AR_LVDS_FRCLK
differential pair class 90_OHM: XDSET_1_D
net class RX_TX: RX1 RX2 RX3 RX4 TX1 TX2 TX3
component class Shunt: Z20 Z21
differential pair AR_LVDS_FRCLK: +AR_LVDS_FRCLK_P -AR_LVDS_FRCLK_N
differential pair AR_LVDS_CLK: +AR_LVDS_CLK_P -AR_LVDS_CLK_N
differential pair AR_LVDS_1: +AR_LVDS_1_P -AR_LVDS_1_N
differential pair AR_LVDS_0: +AR_LVDS_0_P -AR_LVDS_0_N
differential pair XDSET_1_D: +XDSET_1_D_P -XDSET_1_D_N

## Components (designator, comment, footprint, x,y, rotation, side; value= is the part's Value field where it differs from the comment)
C1 "GCM188R71C105KA64D" 0603 2106,2038 r270 top value=1uF
C2 "CGA2B3X7R1H104K050BB" 0402L 2044.9,2028.9 r270 top value=0.1uF
C3 "GCM155R71C224KE02D" 0402L 2352,1745 r270 top value=0.22uF
C4 "GCM155R71C104KA55D" 0402L 2010,1484 r0 top value=0.1uF
C5 "GCM155R71C224KE02D" 0402L 2211.95,1767.6 r270 top value=0.22uF
C6 "GCM155R71C104KA55D" 0402L 2034.5,1705.6 r270 top value=0.1uF
C7 "GCM155R71C224KE02D" 0402L 2218.07,1606.5 r180 bottom value=0.22uF
C8 "GRM033C71A104KE14D" 0201 2137,1566 r90 bottom value=0.1uF
C9 "GJM1555C1H4R7BB01D" 0402L 1842.36,1324.73 r90 top value=4.7pF
C10 "GCM155R71C224KE02D" 0402L 2468,1233 r180 top value=0.22uF
C11 "GCM155R71C104KA55D" 0402L 197.3,1284.9 r270 top value=0.1uF
C12 "GCM155R71C224KE02D" 0402L 2167.2,1209.2 r90 top value=0.22uF
C13 "GCM188R71C105KA64D" 0603 2226.5,1187.9 r90 top value=1uF
C14 "GCM188R71C105KA64D" 0603 2084.45,1189.4 r90 top value=1uF
C15 "GJM1555C1H4R7BB01D" 0402L 1954,1180.4 r0 top value=4.7pF
C16 "C0402C104K8RACTU" 0402L 969.6,920 r0 top value=0.1uF
C17 "GCM21BR71A106KE22L" 0805_HV 2188,1040 r180 top value=10uF
C18 "Capacitor" 0402S 2508,319 r0 bottom value=0.47uF
C19 "CGA5L1X7R0J226M160AC" 1206_180 1712.34,1703.29 r0 bottom value=22uF
C20 "C0402C104K8RACTU" 0402L 967.19,798.85 r0 top value=0.1uF
C21 "CGA6P1X7R1E106M250AC" 1210_280 2249,158 r180 bottom value=10uF
C22 "GCM155R71C104KA55D" 0402 2177,503 r0 bottom value=0.1uF
C23 "06035C473JAT2A" 0603 2382,230 r90 bottom value=0.047uF
C24 "GCM155R71H472KA37D" 0402 1117.1,691.1 r90 top value=4700pF
C25 "CGA6P1X7R1E106M250AC" 1210_280 2731,24 r0 bottom value=10uF
C26 "T491B476K010AT" 3528-21 2689,-59 r0 top value=47uF
C27 "06035C473JAT2A" 0603 2713,116 r0 bottom value=0.047uF
C28 "Capacitor" 0402S 2514.45,28.45 r0 bottom value=0.1uF
C29 "GCM32ER71C226KE19L" 1210_280 2996,218 r0 bottom value=22uF
C30 "GCM32ER71C226KE19L" 1210_280 2996,340 r0 bottom value=22uF
C31 "GCM32ER71C226KE19L" 1210_280 2940,462 r0 bottom value=22uF
C32 "CGA4J1X7R1E475K125AC" 0805L 2445,-5 r270 bottom value=4.7uF
C33 "GCM188R71C105KA64D" 0603 1446,978 r0 bottom value=1uF
C34 "Capacitor" 0402 1445,1029 r180 bottom value=0.1uF
C35 "Capacitor" 0805_HV1 1907,655 r270 bottom value=10uF
C36 "GCM188R71C105KA64D" 0603 1977,658 r90 bottom value=1uF
C37 "CGA5L1X7R0J226M160AC" 1206_180 1417.79,1817.69 r90 bottom value=22uF
C38 "GCM31CR70J226KE23L" 1206_180 2319,892 r180 bottom value=22uF
C39 "GCM155R71C224KE02D" 0402L 2440,1629 r180 bottom value=0.22uF
C40 "GCM21BR71A106KE22L" 0805_HV 1518.99,876.94 r270 bottom value=10uF
C41 "GCM155C71A105KE38D" 0402_070 558.3,1631.85 r90 bottom value=1uF
C42 "C0402C104K8RACTU" 0402L 518.22,1631.85 r270 bottom value=0.1uF
C43 "C0402C104K8RACTU" 0402L 362.52,1629.85 r270 bottom value=0.1uF
C44 "GCM32ER70J476KE19L" 1210_270 1532,1371.13 r0 bottom value=47uF
C45 "GCM21BR71A106KE22L" 0805_HV 2481.19,1533.91 r270 bottom value=10uF
C46 "Capacitor" 0805_HV1 2446.07,657 r270 bottom value=10uF
C47 "GCM155R71C224KE02D" 0402L 2424.67,1506.62 r270 bottom value=0.22uF
C48 "GCM155R71C224KE02D" 0402L 2329,1654 r90 bottom value=0.22uF
C49 "C0402C104K8RACTU" 0402L 894.35,1481.9 r180 bottom value=0.1uF
C50 "C0402C103K4RACTU" 0402L 145.95,1448.7 r270 bottom value=0.01uF
C51 "GCM155R71C224KE02D" 0402L 2387.91,1370.16 r90 bottom value=0.22uF
C52 "GCM21BR71A106KE22L" 0805_HV 2445.08,1380.29 r90 bottom value=10uF
C53 "GCM155R71C224KE02D" 0402L 2072,1342 r0 bottom value=0.22uF
C54 "GCM188R71C105KA64D" 0603 2376.63,659.76 r90 bottom value=1uF
C55 "GCM21BR71A106KE22L" 0805_HV 1729.71,1223.91 r180 bottom value=10uF
C56 "GCM155R71C224KE02D" 0402L 2284.84,1348 r180 bottom value=0.22uF
C57 "GCM155R71C224KE02D" 0402L 2579,1296.68 r90 bottom value=0.22uF
C58 "GCM21BR71A106KE22L" 0805_HV 2642,1282 r90 bottom value=10uF
C59 "Capacitor" 0805_HV 1667,1088 r90 bottom value=10uF
C60 "GCM31CR70J226KE23L" 1206_180 1983.24,893.57 r0 bottom value=22uF
C61 "GCM155C71A105KE38D" 0402_070 127.65,1240.06 r180 bottom value=1uF
C62 "GCM155C71A105KE38D" 0402_070 901,1201 r0 bottom value=1uF
C63 "GCM1555C1H8R0DA16D" 0402L 1006,1150 r0 bottom
C64 "C0402C104K8RACTU" 0402L 903,1159 r180 bottom value=0.1uF
C65 "GCM21BR71A106KE22L" 0805_HV 2416,1183.57 r0 bottom value=10uF
C66 "C0402C103K4RACTU" 0402L 127.19,1130.1 r0 bottom value=0.01uF
C67 "C0402C104K8RACTU" 0402L 127.25,1088.8 r0 bottom value=0.1uF
C68 "GCM31CR70J226KE23L" 1206_180 1980.84,981 r0 bottom value=22uF
C69 "C0402C103K4RACTU" 0402L 127.65,1003.56 r0 bottom value=0.01uF
C70 "GCM1555C1H8R0DA16D" 0402L 1039,983 r0 bottom
C71 "C0402C104K8RACTU" 0402L 814,1010.5 r180 top value=0.1uF
C72 "GCM155R71E103KA37D" 0402S 1519,1232 r0 bottom value=0.01uF
C73 "GCM155R71E103KA37D" 0402S 1562,1004 r0 bottom value=0.01uF
C74 "C1005X7S1A225K050BC" 0402_065L 516.6,857.15 r90 bottom value=2.2uF
C75 "C0402C104K8RACTU" 0402L 473.68,857.15 r90 bottom value=0.1uF
C76 "GCM155C71A105KE38D" 0402_070 364,871 r270 bottom value=1uF
C77 "Capacitor" 0402 2382,562 r0 bottom value=0.1uF
C78 "Capacitor" 0402 2765,460 r0 bottom value=0.1uF
C79 "CGA4J1X7R1E475K125AC" 0805L 2185,11 r270 top value=4.7uF
C80 "GCM21BR71A106KE22L" 0805_HV 2640.38,807 r270 bottom value=10uF
C81 "Capacitor" 0805_HV1 1837,420.37 r270 bottom value=10uF
C82 "0402YC104KAT2A" 0402 2053,502 r180 bottom value=0.1uF
C83 "GCM21BR71A106KE22L" 0805_HV 2477,1114 r90 top value=10uF
C84 "GCM155R71C224KE02D" 0402L 1914,1419 r0 top value=0.22uF
C85 "GRM155R70J105MA12D" 0402 397.9,940.5 r0 top value=1uF
C86 "C1005X7S1A225K050BC" 0402_065L 409.8,1129.1 r180 top value=2.2uF
C87 "GCM188R70J225KE22D" 0603 2261.8,1791.4 r270 top value=2.2uF
C88 "C0402C330J5GAC" 0402L 526,900.4 r0 top value=33pF
C89 "GCM188R70J225KE22D" 0603 1982.1,1728.9 r270 top value=2.2uF
C90 "GCM155R71C224KE02D" 0402L 2182,1128 r90 top value=0.22uF
C91 "C0402C104K8RACTU" 0402L 2041,858 r90 top value=0.1uF
C92 "C0402C104K8RACTU" 0402L 263.6,916.2 r90 top value=0.1uF
C93 "GRT21BR61E226ME13L" 0805_HV 1969,390 r180 bottom value=22uF
C94 "GCM188R71C105KA64D" 0603 2327,400 r90 bottom value=1uF
C95 "GCM21BR71A106KE22L" 0805_HV 1527.13,1485 r0 bottom value=10uF
C96 "GCM21BR71A106KE22L" 0805_HV 1360.21,1328.48 r180 bottom value=10uF
C97 "C0402C104K8RACTU" 0402L 1215,1245 r180 top value=0.1uF
C98 "GCM21BR71A106KE22L" 0805_HV 1569,1654.51 r270 bottom value=10uF
C99 "CGA5L1X7R0J226M160AC" 1206_180 2037.16,1208.67 r180 bottom value=22uF
C100 "GCM21BR71A106KE22L" 0805_HV 2293,1838 r270 bottom value=10uF
C101 "GCM155R71E103KA37D" 0402L 2010,1448 r180 top value=0.01uF
C102 "GCM21BR71A106KE22L" 0805_HV 2654.2,1941.82 r90 bottom value=10uF
C103 "GCM21BR71A106KE22L" 0805_HV 1335.31,1654.61 r270 bottom value=10uF
C104 "GCM21BR71A106KE22L" 0805_HV 2097.09,1095.42 r270 bottom value=10uF
C105 "CGA5L1X7R0J226M160AC" 1206_180 1754.95,1312 r180 bottom value=22uF
"CAUTION HOT SURFACE" "CAUTION HOT SURFACE" IEC_HotSurface_Small 1560,1751 r0 top
D2 "SMS3923-040LF" SOD-882 53.73,1105.47 r0 top value=V
D5 "APHHS1005CGCK" APHHS1005_Green 105,676 r90 top value=Green
DS1 "LS L29K-G1J2-1-Z" "LS L29K_Red" 157,676 r90 top value=Red
DS2 "LS L29K-G1J2-1-Z" "LS L29K_Red" 52,676 r270 top value=Red
DS3 "SML-E12Y8WT86" SML-E1_Yellow -18,676 r270 top value=Yellow
DS4 "SML-E12Y8WT86" SML-E1_Yellow 255.6,468.46 r270 top value=Yellow
"ESD Susceptible" "ESD Susceptible" ESD_Overlay_Small 960,1123 r0 top
F1 "0440005.WR" 1206 2127,127 r180 top
FID1 "Fiducial" FIDUCIAL10-20 196,-40.5 r90 top
FID2 "Fiducial" FIDUCIAL10-20 196,2287.5 r90 top
FID3 "Fiducial" FIDUCIAL10-20 3007,1857 r90 top
FID4 "Fiducial" FIDUCIAL10-20 196,2287.5 r90 bottom
FID5 "Fiducial" FIDUCIAL10-20 196,-40.5 r90 bottom
FID6 "Fiducial" FIDUCIAL10-20 3007,1857 r90 bottom
J1 "QSH-030-01-L-D-A" SAMTEC_QSH-030-01-X-D-A 813.64,1886.26 r270 top locked
J2 "128-0711-201" JOHNSON_128-0711-201 2159,252 r0 top
J3 "OSTTE030161" ON-SHORE_OSTTE030161 670.6,-25.28 r180 bottom
J5 "SSM-110-S-DV" SAMTEC_SSM-110-X-DV 977.5,2109.5 r0 bottom locked
J6 "SSM-110-S-DV" SAMTEC_SSM-110-X-DV 977.5,409.5 r0 bottom
J8 "105017-0001" CONN_105017-0001 1945,-131.01 r180 bottom
L1 "XAL5030-222MEB" XAL5030 2790,279 r0 bottom value=2.2uH
L2 "DFE252012PD-R47M" DFE252012P 2347,797 r0 bottom value=470nH
L3 "DFE252012PD-R47M" DFE252012P 1971,798.35 r180 bottom value=470nH
L4 "DFE252012PD-1R0M" DFE252012P 1937,496 r90 bottom value=1uH
L5 "NLCV32T-R10M-EFRD" NLCV32 1809.37,1080.62 r90 bottom value=100nH
L6 "NLCV32T-R10M-EFRD" NLCV32 2212.35,1090.07 r90 bottom value=100nH
L7 "HI2220P601R-10" 2220_345 2376,19 r270 top value="600 ohm"
L8 "BLM18KG121TH1D" 0603 1492.32,1657.42 r90 bottom value="120 ohm"
L9 "BLM18KG121TH1D" 0603 1430.22,1657.42 r90 bottom value="120 ohm"
L10 "NLCV32T-R10M-EFRD" NLCV32 2538.67,767.5 r90 bottom value=100nH
LBL1 "Label" Label_650x200 2821,382 r0 top
Logo1 "Texas Instruments" TI_STACKED_OVERLAY_SMALL 668,1043 r90 top
Logo2 "FCC disclaimer" FCC_disclaimer 2420,2373 r0 top
LOGO3 "CE Mark" CE_Mark_5mm 1840,2250 r180 bottom
Logo4 "WEEE logo" WEEE_Minimum 2156,2270 r180 bottom
P1 "TSW-103-07-T-S" Samtec_TSW-103-07-T-S 6.27,1746.15 r270 top
P6 "PJ-051AH" CUI_PJ-051AH 1245.91,-136.37 r270 bottom
P7 "TSW-102-07-G-S" TSW-102-07-G-S 171.94,1796.15 r270 top
Q1 "BSS123" SOT-23 120.58,536.75 r90 top value=100V
Q2 "BSS123" SOT-23 130,394 r0 bottom value=100V
R1 "CRCW02010000Z0ED" 0201_Silk 1100,2347 r270 bottom value=0
R2 "CRCW02010000Z0ED" 0201_Silk 930.05,2242.72 r270 top value=0
R3 "CRCW040210K0FKED" 0402L 1884.3,857.1 r180 top value=10.0k
R4 "CRCW02010000Z0ED" 0201_Silk 1022.55,2242.72 r270 top value=0
R5 "CRCW02010000Z0ED" 0201_Silk 1921,937 r0 top value=0
R6 "CRCW02010000Z0ED" 0201_Silk 1128.05,2242.72 r270 top value=0
R7 "CRCW02010000Z0ED" 0201_Silk 1161.25,2242.72 r270 top value=0
R8 "CRCW02010000Z0ED" 0201_Silk 1348,2318 r90 bottom value=0
R9 "CRCW02010000Z0ED" 0201_Silk 829.75,2241.72 r270 top value=0
R10 "CRCW02010000Z0ED" 0201_Silk 1239.25,2241.72 r270 top value=0
R11 "ERJ-2GE0R00X" 0402L 1165,1080 r270 top value=0
R12 "ERJ-2GE0R00X" 0402L 900,1237 r270 top value=0
R13 "CRCW040210K0FKED" 0402L 1198.4,2234.05 r270 top value=10.0k
R14 "CRCW040210K0FKED" 0402L 1042.9,2342.6 r180 bottom value=10.0k
R15 "CRCW040210K0FKED" 0402L 1114,2137.85 r270 top value=10.0k
R16 "CRCW040210K0FKED" 0402L 649,1846 r180 bottom value=10.0k
R17 "CRCW02010000Z0ED" 0201_Silk 1082,2242.72 r90 top value=0
R18 "CRCW02010000Z0ED" 0201_Silk 1028.21,2130.07 r270 top value=0
R19 "CRCW02010000Z0ED" 0201_Silk 419.25,2129.72 r270 top value=0
R20 "CRCW02010000Z0ED" 0201_Silk 452.11,2129.72 r270 top value=0
R21 "CRCW02010000Z0ED" 0201_Silk 484.35,2129.72 r270 top value=0
R22 "CRCW02010000Z0ED" 0201_Silk 550.11,2129.72 r270 top value=0
R23 "CRCW02010000Z0ED" 0201_Silk 582.61,2129.72 r270 top value=0
R24 "CRCW02010000Z0ED" 0201_Silk 641.1,1885.6 r180 bottom value=0
R25 "CRCW02010000Z0ED" 0201_Silk 755.8,1883.8 r180 bottom value=0
R26 "CRCW02010000Z0ED" 0201_Silk 866.7,2129.6 r270 top value=0
R27 "CRCW02010000Z0ED" 0201_Silk 898.8,2129.5 r270 top value=0
R28 "CRCW02010000Z0ED" 0201_Silk 931.5,2129.4 r270 top value=0
R29 "CRCW02010000Z0ED" 0201_Silk 963.83,2129.72 r270 top value=0
R30 "CRCW02010000Z0ED" 0201_Silk 995.75,2129.72 r270 top value=0
R31 "CRCW02010000Z0ED" 0201_Silk 1176.75,2129.72 r270 top value=0
R32 "CRCW02010000Z0ED" 0201_Silk 1276,2129 r270 top value=0
R33 "CRCW02010000Z0ED" 0201_Silk 517.39,2129.28 r270 top value=0
R34 "CRCW20100000Z0EF" 2010 1433,2072 r0 top value=0
R35 "CRCW02010000Z0ED" 0201_Silk 1334,1971 r90 top value=0
R36 "CRCW02010000Z0ED" 0201_Silk 1427.25,1976.72 r90 top value=0
R37 "ERJ-2GE0R00X" 0402L 2160,2028 r270 top value=0
R38 "CRCW040247K5FKED" 0402L 1687.8,2021.84 r180 top value=47.5k
R39 "CRCW020133R2FNED" 0201_Silk 1656.9,1944.5 r90 top value=33.2
R40 "CRCW020133R2FNED" 0201_Silk 2050,1960 r0 top value=33.2
R41 "CRCW040210K0FKED" 0402L 2118.55,1950.98 r0 top value=10.0k
R42 "CRCW020133R2FNED" 0201_Silk 1708.5,1942.8 r90 top value=33.2
R43 "CRCW040210K0FKED" 0402L 1683.2,1892 r180 top value=10.0k
R44 "CRCW020133R2FNED" 0201_Silk 2049.68,1920.35 r0 top value=33.2
R45 "CRCW020133R2FNED" 0201_Silk 2050.68,1873.85 r0 top value=33.2
R46 "CRCW04020000Z0ED" 0402 2629.9,1729.72 r270 bottom value=0
R47 "Resistor" 0402L 1911,1474 r180 top value=0
R48 "CRCW02010000Z0ED" 0201_Silk 475.61,1611.72 r270 top value=0
R49 "CRCW02010000Z0ED" 0201_Silk 508.25,1611.72 r270 top value=0
R50 "CRCW02010000Z0ED" 0201_Silk 540.75,1611.72 r270 top value=0
R51 "CRCW02010000Z0ED" 0201_Silk 573.25,1611.72 r270 top value=0
R52 "CRCW02010000Z0ED" 0201_Silk 605.75,1611.72 r270 top value=0
R53 "CRCW02010000Z0ED" 0201_Silk 638.25,1611.72 r270 top value=0
R54 "CRCW020120R0FNED" 0201_033 984,1874 r90 bottom value=20.0
R55 "CRCW020120R0FNED" 0201_033 951,1873.8 r90 bottom value=20.0
R56 "CRCW020120R0FNED" 0201_033 918.5,1873.3 r90 bottom value=20.0
R57 "CRCW020120R0FNED" 0201_033 885.6,1873.3 r90 bottom value=20.0
R58 "CRCW02010000Z0ED" 0201_Silk 800.55,1611.72 r270 top value=0
R59 "CRCW02010000Z0ED" 0201_Silk 833.05,1611.72 r270 top value=0
R60 "CRCW02010000Z0ED" 0201_Silk 688,2235 r270 top value=0
R61 "ERJ-2RKF1002X" 0402 525.8,941.1 r180 top value=10.0k
R62 "CRCW02010000Z0ED" 0201_Silk 929.85,1611.72 r270 top value=0
R63 "CRCW02010000Z0ED" 0201_Silk 962.11,1611.72 r270 top value=0
R64 "CRCW02010000Z0ED" 0201_Silk 1026.61,1611.72 r270 top value=0
R65 "CRCW02010000Z0ED" 0201_Silk 1059.25,1611.72 r270 top value=0
R66 "CRCW02010000Z0ED" 0201_Silk 1091.75,1611.72 r270 top value=0
R67 "CRCW02010000Z0ED" 0201_Silk 1124.25,1611.72 r270 top value=0
R68 "ERJ-2GEJ101X" 0402L 246.04,1553.15 r90 top value=100
R69 "CRCW02010000Z0ED" 0201_Silk 1059.25,1551.72 r270 top value=0
R70 "CRCW02010000Z0ED" 0201_Silk 1091.75,1552.14 r270 top value=0
R71 "CRCW02010000Z0ED" 0201_Silk 1124.33,1551.72 r270 top value=0
R72 "CRCW02010000Z0ED" 0201_Silk 192.5,1461.25 r90 top value=0
R73 "CRCW040210K0FKED" 0402L 192.05,1390.92 r90 top value=10.0k
R74 "CRCW040210K0FKED" 0402L 51.65,1221.14 r180 top value=10.0k
R75 "CRCW02010000Z0ED" 0201_Silk 1250,1176 r270 top value=0
R76 "CRCW02010000Z0ED" 0201_Silk 1284,1176 r270 top value=0
R77 "ERJ-2GEJ101X" 0402L 45,1258 r0 top value=100
R78 "ERJ-2GE0R00X" 0402L 970,880 r180 top value=0
R79 "ERJ-2GEJ101X" 0402L 242.25,1153.14 r180 top value=100
R80 "ERJ-2GEJ101X" 0402L -27.26,1087.15 r90 top value=100
R81 "Resistor" 0402L 2141,1309 r180 bottom value=0
R82 "Resistor" 0402L 2570,13 r90 bottom value=10k
R83 "CRCW060320R0JNEA" 0603 1388.84,1205.26 r0 bottom value=20
R84 "CRCW0402100KJNED" 0402 2392,77 r0 bottom value=100k
R85 "CRCW040261R9FKED" 0402L 1158,690.8 r90 top value=61.9
R86 "CRCW040210K0FKED" 0402L 1246.3,794.7 r270 top value=10.0k
R87 "CRCW040261R9FKED" 0402L 1076.7,691.4 r270 top value=61.9
R88 "CRCW040282K5FKED" 0402L 966.12,663.85 r270 top value=82.5k
R89 "CRCW040210K0FKED" 0402L 1006.58,663.55 r270 top value=10.0k
R90 "ERJ-2GEJ361X" 0402L 207,771 r90 top value=360
R91 "CRCW040210K0FKED" 0402L 156,773 r90 bottom value=10.0k
R92 "CRCW04027K87FKED" 0402L 965.62,585.85 r270 top value=7.87k
R93 "CRCW0402750RFKED" 0402L 1005.82,585.85 r270 top value=750
R94 "CRCW02010000Z0ED" 0201_Silk 828.25,532.28 r90 top value=0
R95 "CRCW04027K87FKED" 0402L 648.82,524.55 r90 top value=7.87k
R96 "CRCW040282K5FKED" 0402L 608.78,524.25 r270 top value=82.5k
R97 "ERJ-2GE0R00X" 0402L 276.14,576.76 r90 top value=0
R98 "CRCW040210K0FKED" 0402L 316,575 r90 top value=10.0k
R99 "CRCW04027K87FKED" 0402L 297,629 r180 top value=7.87k
R100 "CRCW04020000Z0ED" 0402 2649,1807.44 r0 bottom value=0
R101 "CRCW0402750RFKED" 0402L 366.98,572.85 r90 top value=750
R102 "CRCW02010000Z0ED" 0201_Silk 1230.25,500.28 r90 top value=0
R103 "ERJ-2GEJ361X" 0402L -18,580 r270 top value=360
R104 "CRCW02010000Z0ED" 0201_Silk 727.75,499.28 r90 top value=0
R105 "CRCW02010000Z0ED" 0201_Silk 929.75,499.28 r90 top value=0
R106 "CRCW02010000Z0ED" 0201_Silk 1030.25,499.28 r90 top value=0
R107 "ERJ-2GE0R00X" 0402L 1129.75,499.28 r90 top value=0
R108 "CRCW02010000Z0ED" 0201_Silk 1330.35,499.08 r90 top value=0
R109 "CRCW02010000Z0ED" 0201_Silk 1367.85,499.08 r90 top value=0
R110 "CRCW0402100KFKED" 0402L 7.72,523.77 r180 top value=100k
R111 "CRCW02010000Z0ED" 0201_Silk 2143,369 r0 top value=0
R112 "CRCW0402750RFKED" 0402L 649.32,447.55 r270 top value=750
R113 "CRCW040210K0FKED" 0402L 608.92,447.55 r90 top value=10.0k
R114 "CRCW040282K5FKED" 0402L 297,664 r0 top value=82.5k
R115 "CRCW20100000Z0EF" 2010 720,722 r0 bottom value=0
R116 "ERJ-2GEJ511X" 0402L 7.78,480.33 r0 top value=510
R117 "ERJ-2GEJ361X" 0402L 308.61,456.15 r90 top value=360
R118 "CRCW0402220RJNED" 0402 88,783 r270 bottom value=220
R119 "Resistor" 0402L 2272,347.69 r90 bottom value=0
R120 "Resistor" 0402L 1584,1038 r180 bottom value=0
R121 "Resistor" 0402L 2224,351 r90 bottom value=0
R122 "ERA-2AEB1212X" 0402 1509,1273 r180 bottom value=12.1k
R123 "CRCW04021K00FKED" 0402L 757.28,1632.15 r90 bottom value=1.00k
R124 "CRCW04021K00FKED" 0402L 637.72,1631.85 r270 bottom value=1.00k
R125 "CRCW04024K87FKED" 0402L 677.52,1631.85 r270 bottom value=4.87k
R126 "CRCW04021K00FKED" 0402L 717.68,1632.15 r90 bottom value=1.00k
R127 "CRCW04021K00FKED" 0402L 598.12,1631.85 r270 bottom value=1.00k
R128 "ERJ-2GE0R00X" 0402L 246.5,1628.85 r270 bottom value=0
R129 "ERJ-2GE0R00X" 0402L 287,1628.5 r270 bottom value=0
R130 "MCT06030Z0000ZP500" 0603 2557,522 r0 bottom value=0
R131 "Resistor" 0402S 2179,812 r90 bottom value=3.3k
R132 "Resistor" 0402S 2144,812 r90 bottom value=3.3k
R133 "MCT06030Z0000ZP500" 0603 2750,520 r180 bottom value=0
R134 "CRCW040249R9FKED" 0402L 894.65,1440.6 r0 bottom value=49.9
R135 "CRCW02010000Z0ED" 0201_Silk 134.78,1366.19 r0 bottom value=0
R136 "CRCW02010000Z0ED" 0201_Silk 134.78,1334.29 r0 bottom value=0
R137 "MCT06030Z0000ZP500" 0603 2498,1258 r180 bottom value=0
R138 "CRCW0402100KFKED" 0402L 2545,396 r90 bottom value=100k
R139 "ERA-2AEB4871X" 0402 2664,414 r180 bottom value=4.87k
R140 "CRCW04021K00FKED" 0402L 127.65,1199.52 r0 bottom value=1.00k
R141 "ERJ-2GE0R00X" 0402L 2579,396 r90 bottom value=0
R142 "CRCW040210K0JNED" 0402 2150,453 r0 bottom value=10k
R143 "Resistor" 0402L 2421,404 r90 bottom value=0
R144 "Resistor" 0402L 1828,600 r270 bottom value=0
R145 "ERA-2AEB4872X" 0402 1606,1280.92 r180 bottom value=48.7k
R146 "ERA-2ARB4421X" 0402 2560.62,460 r180 bottom value=4.42k
R147 "CRCW04020000Z0ED" 0402 1276,2331 r180 bottom value=0
R148 "Resistor" 0402L 2062,315 r270 bottom value=0
R149 "Resistor" 0402L 2098,314 r270 bottom value=0
R150 "CRCW0402100RFKED" 0402 2381.32,514.32 r0 bottom value=100
R151 "CRCW0402330KFKED" 0402L 127.65,961.04 r180 bottom value=330k
R152 "ERJ-2GE0R00X" 0402L 814,1071.5 r0 top value=0
R153 "CRCW0402330KFKED" 0402L 127.65,917.74 r0 bottom value=330k
R154 "ERJ-2GEJ101X" 0402L 796,936 r270 top value=100
R155 "CRCW040210K0FKED" 0402L 692.78,861.15 r90 bottom value=10.0k
R156 "CRCW20100000Z0EF" 2010 2752,628.3 r180 bottom value=0
R157 "CRCW04020000Z0ED" 0402 2663,460 r180 bottom value=0
R158 "CRCW040210K0FKED" 0402 2269,440 r270 bottom value=10.0k
R159 "Resistor" 0402L 2386,404 r90 bottom value=0
R160 "ERJ-2GEJ511X" 0402L 13,480 r0 bottom value=510
R161 "MCT06030Z0000ZP500" 0603 2000,54 r90 bottom value=0
R162 "CRCW02010000Z0ED" 0201_Silk 1475,351 r180 top value=0
R163 "CRCW02010000Z0ED" 0201_Silk 1377,366 r180 top value=0
R164 "CRCW02010000Z0ED" 0201_Silk 1278,367 r180 top value=0
R165 "CRCW02010000Z0ED" 0201_Silk 895,1612 r90 top value=0
R166 "CRCW02010000Z0ED" 0201_Silk 832.75,169.28 r90 bottom value=0
R167 "CRCW02010000Z0ED" 0201_Silk 2033.6,804.6 r180 top value=0
R168 "CRCW02010000Z0ED" 0201_Silk 2039,928 r90 top value=0
R169 "CRCW02010000Z0ED" 0201_Silk 685.13,169.28 r90 bottom value=0
R170 "CRCW04022K94FKED" 0402 1473,441 r0 top value=2.94k
R171 "CRCW04022K94FKED" 0402 1473,393 r0 top value=2.94k
R172 "CRCW0402100KFKED" 0402L 874,162 r90 bottom value=100k
R173 "CRCW0402100KFKED" 0402L 759.88,161.15 r90 bottom value=100k
R174 "CRCW040230K0FKED" 0402L 2046,156 r90 bottom value=30.0k
R175 "MCT06030Z0000ZP500" 0603 1795,-7 r0 bottom value=0
R177 "CRCW040210K0FKED" 0402L 1246.5,870.35 r270 top value=10.0k
R178 "ERJ-2GE0R00X" 0402L 1200.8,690.6 r270 top value=0
R179 "CRCW020120R0FNED" 0201_033 811,2130.5 r270 top value=20.0
R180 "CRCW020120R0FNED" 0201_033 778,2128 r270 top value=20.0
R181 "CRCW020120R0FNED" 0201_033 753.5,2234.3 r270 top value=20.0
R182 "CRCW020120R0FNED" 0201_033 745,2122 r270 top value=20.0
R183 "CRCW020120R0FNED" 0201_033 721,2234.7 r270 top value=20.0
R184 "CRCW020120R0FNED" 0201_033 712,2130 r270 top value=20.0
R186 "CRCW040210K0JNED" 0402 1752,516 r0 bottom value=10k
R188 "Resistor" 0402L 1622,541 r180 bottom value=0
R189 "Resistor" 0402L 1724,582 r180 bottom value=0
R190 "CRCW040210K0JNED" 0402 1724,629 r0 bottom value=10k
R193 "CRCW040226K1FKED" 0402 544.7,1010.32 r270 top value=26.1k
R194 "CRCW040210K0FKED" 0402L 544.7,1099.34 r270 top value=10.0k
R196 "ERJ-2GE0R00X" 0402L 2098,858 r270 top value=0
R197 "CRCW040210K0FKED" 0402L 177.8,1016.4 r270 top value=10.0k
R198 "CRCW02010000Z0ED" 0201_Silk 303.6,1075.8 r180 top value=0
R199 "CRCW02010000Z0ED" 0201_Silk 300.3,934.8 r270 top value=0
R200 "ERJ-2GE0R00X" 0402L 222.7,916.3 r270 top value=0
R201 "CRCW02010000Z0ED" 0201_Silk 184.9,924.2 r270 top value=0
R202 "ERJ-2GEJ361X" 0402L 45,780 r90 bottom value=360
R208 "CRCW040210K0FKED" 0402L 1269,1253 r90 top value=10.0k
S1 "219-3MST" SW_219-3MST 596,205 r180 top
S2 "CJS-1201TA" SW_CJS_1201A 1424,1177 r180 top
SW1 "KMR243GLFG" SW_KMR243GLFG 336.65,1431.62 r180 top
SW2 "KMR243GLFG" SW_KMR243GLFG 335.7,1256 r180 top
TP1 "5001" Keystone5001 -5,224 r0 top
TP2 "TP_H0.45P0.75" TP_H045P075 1597.88,1231.78 r90 bottom
TP3 "5001" Keystone5001 984.57,-164.22 r90 bottom
U1 "MX25V1635FZNQ" WSON-8L_6x5MM_EP 1875.13,1947.18 r0 top
U2 "AWR1843ABL" ABL0161B 2294.55,1477.9 r180 top locked
U3 "TCAN1042HGVDQ1" D0008A_L 1116.31,902.98 r270 top
U4 "LP87702DRHBRQ1" RHB0032N 2171.27,651.27 r90 bottom
U5 "TPS7A5301QRGRRQ1" RGR0020A 1541.04,1134 r270 bottom
U6 "TM4C1294NCPDTT3" PDT0128A 511.79,1248.04 r0 bottom
U7 "LM4040C25QDBZR" DBZ0003A_N 8.08,1177.09 r180 bottom
U8 "LMS36x5" RNL0022A_NV 2535,177.72 r0 bottom
U10 "TPD4E004DRYR" DRY0006A 1976,276.76 r270 top
U11 "TPS79601DRBR" DRB0008B 436.9,1034.5 r0 top
U12 "TMP112AIDRLR" DRL0006A 1972.5,876.9 r0 top
U13 "TMP112AIDRLR" DRL0006A 240,1005.4 r270 top
U14 "TS3A5018RSVR" RSV0016A 1103,1268 r270 top
Y1 "CX3225SA40000D0PTWCC" KYOCERA_CX3225SA 1928,1281 r0 top
Y2 "NX3225SA-16.000M-STD-CRS-2" NDK_NX3225SA 973.46,1070.04 r270 bottom
ZZ1 "This Assembly Note is for PCB labels only" AssemblyNoteLabel -117.91,3554.91 r0 top
ZZ2 "These assemblies are ESD sensitive, ESD precautions shall be observed." AssemblyNote -118.31,3480.14 r0 top
ZZ3 "These assemblies must be clean and free from flux and all contaminants. Use of no clean flux is not acceptable." AssemblyNote -117.52,3404.58 r0 top
ZZ4 "These assemblies must comply with workmanship standards IPC-A-610 Class 2, unless otherwise specified." AssemblyNote -116.32,3327.82 r0 top
ZZ5 "Micro USB cable, Brackets, Screws, Nuts, Jumpers and Bump on need to be placed in a plastic bag" AssemblyNote -115.53,3255.05 r0 top

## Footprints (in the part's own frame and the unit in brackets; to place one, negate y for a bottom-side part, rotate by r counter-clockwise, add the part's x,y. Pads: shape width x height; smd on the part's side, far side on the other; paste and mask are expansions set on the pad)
0201 [mm] "Data from Kemet datasheet CC101_COM dated 7/28/11"
  rect 0.46x0.42 smd mask+0.048: 1(-0.33,0) 2(0.33,0)
  body extent -0.31,-0.16 0.31,0.16, height 0.26
0201_033 [mm] "SMD, 2-Leads, Height 0.33mm"
  rect 0.46x0.42 smd mask+0: 1(-0.33,0) 2(0.33,0)
  body extent -0.31,-0.16 0.31,0.16, height 0.33
0201_Silk [mm] "Data from Kemet datasheet CC101_COM dated 7/28/11"
  rect 0.46x0.42 smd mask+0: 1(-0.33,0) 2(0.33,0)
  silkscreen extent -0.75,-0.4 0.75,0.4, body extent -0.31,-0.16 0.31,0.16, height 0.26
0402 [mm] "0402 from SM-752 data"
  rect 0.8x0.6 smd: 1(-0.6,0) 2(0.6,0)
  silkscreen extent -1.22,-0.52 1.22,0.52, body extent -0.55,-0.3 0.55,0.3, height 0.6
0402_065L [mm] "0402"
  rect 0.6x0.5 smd: 1(-0.5,0) 2(0.5,0)
  body extent -0.55,-0.3 0.55,0.3, height 0.65
0402_070 [mil] "SMD, 2-Leads, Body 1.2x0.7mm, Height 0.7mm"
  rect 15x24 smd: 1(-20,0) 2(20,0)
  body extent -24,-14 24,14, height 28
0402L [mm] "0402 from SM-752 data"
  rect 0.6x0.5 smd: 1(-0.5,0) 2(0.5,0)
  body extent -0.55,-0.3 0.55,0.3, height 0.6
0402S [mil] "Based on C0402S footprint from PADS legacy"
  rect 15x24 smd: 1(-20,0) 2(20,0)
  body extent -22,-12 22,12, height 24
0603 [mm] "0603 from SM-752 data"
  rect 1x0.95 smd: 1(-0.8,0) 2(0.8,0)
  silkscreen extent -1.52,-0.69 1.52,0.69, body extent -0.87,-0.47 0.87,0.47, height 1
0805_HV [mil] "0805 with 30mil clearance between pads"
  rect 50x63 smd: 1(-40,0) 2(40,0)
  silkscreen extent -74,-40 74,40, body extent -43,-29 43,29, height 57
0805_HV1 [mm] "Custom footprint based on analyzing multiple manufacturer recommendations"
  rrect10% 1x1.25 smd: 1(-1,0) 2(1,0)
  silkscreen extent -0.2,-0.75 0.2,0.75, body extent -1.1,-0.72 1.1,0.73, height 1.45
0805L [mm] "0805 from SM-752 data"
  rect 1.1x1.4 smd: 1(-0.75,0) 2(0.75,0)
  body extent -1.1,-0.72 1.1,0.72, height 1.45
1206 [mm] "1206 from SM-752 data"
  rect 1.3x1.85 smd: 1(-1.45,0) 2(1.45,0)
  silkscreen extent -2.4,-1.21 2.4,1.21, body extent -1.7,-0.9 1.7,0.9, height 1.35
1206_180 [mm] "1206_180"
  rect 1.1x1.6 smd: 1(-1.7,0) 2(1.7,0)
  silkscreen extent -0.9,-1 0.9,1, body extent -1.75,-0.95 1.75,0.95, height 1.8
1210_270 [mm] "1210"
  rect 1.3x2.7 smd: 1(-1.45,0) 2(1.45,0)
  silkscreen extent -2.32,-1.57 2.32,1.57, body extent -1.7,-1.35 1.7,1.35, height 2.7
1210_280 [mm] "SMD, 2-Leads, Body 3.6x2.8mm, Height 2.8mm"
  rect 1.1x2.2 smd: 1(-1.65,0) 2(1.65,0)
  silkscreen extent -0.84,-1.4 0.84,1.4, body extent -1.8,-1.4 1.8,1.4, height 2.8
2010 [mm] "Chip Capacitor, Body 5.08x2.54mm, IPC Medium Density"
  rect 1.6x2.7 smd: 1(-2.3,0) 2(2.3,0)
  silkscreen extent -3.42,-1.65 3.42,1.65, body extent -2.73,-1.45 2.73,1.45, height 1.66
2220_345 [mm] "Wurth recommended land pattern"
  rrect3% 3.05x6.1 smd: 1(-3.075,0) 2(3.075,0)
  silkscreen extent -1.3,-3 1.3,3, body extent -2.8,-2.54 2.79,2.54, height 3.21
3528-21 [mm] "Medium Density IPC, based on Kemet datasheet 2016-10-20"
  rrect6% 1.8x2.23 smd: 1(-1.46,0) 2(1.46,0)
  silkscreen extent -2.29,-1.5 0.76,1.5, body extent -1.85,-1.5 1.85,1.5, height 2.12
ABL0161B [mm] "BGA, 161-Balls, Body 10.4x10.4mm, Pitch 0.65mm"
  round 0.32 smd: A1(-4.55,4.55) A2(-3.9,4.55) A3(-3.25,4.55) A5(-1.95,4.55) A7(-0.65,4.55) A9(0.65,4.55) A10(1.3,4.55) A13(3.25,4.55) A14(3.9,4.55) A15(4.55,4.55) B1(-4.55,3.9) B2(-3.9,3.9) B3(-3.25,3.9) B4(-2.6,3.9) B5(-1.95,3.9) B6(-1.3,3.9) B7(-0.65,3.9) B8(0,3.9) B9(0.65,3.9) B10(1.3,3.9) B11(1.95,3.9) B12(2.6,3.9) B13(3.25,3.9) B14(3.9,3.9) B15(4.55,3.9) C1(-4.55,3.25) C2(-3.9,3.25) C3(-3.25,3.25) C4(-2.6,3.25) C5(-1.95,3.25) C6(-1.3,3.25) C7(-0.65,3.25) C8(0,3.25) C9(0.65,3.25) C13(3.25,3.25) C14(3.9,3.25) C15(4.55,3.25) D2(-3.9,2.6) D13(3.25,2.6) D14(3.9,2.6) D15(4.55,2.6) E1(-4.55,1.95) E2(-3.9,1.95) E3(-3.25,1.95) E5(-1.95,1.95) E6(-1.3,1.95) E8(0,1.95) E10(1.3,1.95) E11(1.95,1.95) E13(3.25,1.95) E14(3.9,1.95) E15(4.55,1.95) F2(-3.9,1.3) F3(-3.25,1.3) F5(-1.95,1.3) F9(0.65,1.3) F11(1.95,1.3) F13(3.25,1.3) F14(3.9,1.3) F15(4.55,1.3) G1(-4.55,0.65) G2(-3.9,0.65) G3(-3.25,0.65) G5(-1.95,0.65) G6(-1.3,0.65) G7(-0.65,0.65) G8(0,0.65) G10(1.3,0.65) G13(3.25,0.65) G14(3.9,0.65) G15(4.55,0.65) H2(-3.9,0) H3(-3.25,0) H5(-1.95,0) H7(-0.65,0) H9(0.65,0) H11(1.95,0) H13(3.25,0) H14(3.9,0) H15(4.55,0) J1(-4.55,-0.65) J2(-3.9,-0.65) J3(-3.25,-0.65) J5(-1.95,-0.65) J6(-1.3,-0.65) J7(-0.65,-0.65) J8(0,-0.65) J10(1.3,-0.65) J13(3.25,-0.65) J14(3.9,-0.65) J15(4.55,-0.65) K2(-3.9,-1.3) K3(-3.25,-1.3) K5(-1.95,-1.3) K7(-0.65,-1.3) K8(0,-1.3) K9(0.65,-1.3) K10(1.3,-1.3) K11(1.95,-1.3) K13(3.25,-1.3) K14(3.9,-1.3) K15(4.55,-1.3) L1(-4.55,-1.95) L2(-3.9,-1.95) L3(-3.25,-1.95) L5(-1.95,-1.95) L6(-1.3,-1.95) L8(0,-1.95) L10(1.3,-1.95) L13(3.25,-1.95) L14(3.9,-1.95) L15(4.55,-1.95) M2(-3.9,-2.6) M3(-3.25,-2.6) M14(3.9,-2.6) M15(4.55,-2.6) N1(-4.55,-3.25) N2(-3.9,-3.25) N3(-3.25,-3.25) N4(-2.6,-3.25) N5(-1.95,-3.25) N6(-1.3,-3.25) N7(-0.65,-3.25) N8(0,-3.25) N9(0.65,-3.25) N10(1.3,-3.25) N11(1.95,-3.25) N12(2.6,-3.25) N13(3.25,-3.25) N14(3.9,-3.25) N15(4.55,-3.25) P1(-4.55,-3.9) P2(-3.9,-3.9) P3(-3.25,-3.9) P4(-2.6,-3.9) P5(-1.95,-3.9) P6(-1.3,-3.9) P7(-0.65,-3.9) P8(0,-3.9) P9(0.65,-3.9) P10(1.3,-3.9) P11(1.95,-3.9) P12(2.6,-3.9) P13(3.25,-3.9) P14(3.9,-3.9) P15(4.55,-3.9) R1(-4.55,-4.55) R2(-3.9,-4.55) R3(-3.25,-4.55) R4(-2.6,-4.55) R5(-1.95,-4.55) R6(-1.3,-4.55) R7(-0.65,-4.55) R8(0,-4.55) R9(0.65,-4.55) R10(1.3,-4.55) R11(1.95,-4.55) R12(2.6,-4.55) R13(3.25,-4.55) R14(3.9,-4.55) R15(4.55,-4.55)
  silkscreen extent -5.3,-5.3 5.3,5.3, body extent -5.2,-5.2 5.2,5.2, height 0.62
APHHS1005_Green [mm] "SMD, 2-Leads, Body 1x0.5mm"
  rrect20% 0.7x0.5 smd: 1(-0.45,0) 2(0.45,0)
  silkscreen extent -0.8,-0.65 1.2,0.65, body extent -0.5,-0.25 0.5,0.25, height 0.5
AssemblyNote [mil] "Assembly Note"
AssemblyNoteLabel [mil] "Assembly Note for PCB Labels"
CE_Mark_5mm [mil] "Minimum text height for CE Mark"
  silkscreen extent -138,-98 138,98
CONN_105017-0001 [mm] "Molex Micro USB-B"
  rect 0.4x1.35 smd: 1(-1.3,1.35) 2(-0.65,1.35) 3(0,1.35) 4(0.65,1.35) 5(1.3,1.35)
  oval 1.2x1.9 hole 0.6 slot 1.3 at 90 deg: 6(-3.5,-1.35) 9(3.5,-1.35)
  rect 1.5x1.9 smd: 7(-1,-1.35) 8(1,-1.35)
  round 1.45 hole 0.85: 10(2.5,1.35) 11(-2.5,1.35)
  TOP region: -3.5,-0.4 -2.3,-0.4 -2.3,-2.3 -3.5,-2.3
  TOP region: 3.5,-2.3 2.3,-2.3 2.3,-0.4 3.5,-0.4
  silkscreen extent -4.1,-0.2 4.1,1.4, body extent -4.1,-3.93 4.1,1.5, height 2.72
CUI_PJ-051AH [mm] "DC Power Jack, R/A, TH"
  rrect8% 2.4x1.2 hole 0.8 square: 1(-6.3,3.3) 2(-6.3,-5.3) 3(-6.3,-0.1)
  rrect8% 2.7x1.2 hole 0.8 square: 4(1,-6.2) 5(1,3.7)
  rrect7% 1.5x1.5 hole 1.8 square unplated mask+0.102: MH1(0,0)
  body extent -7.75,-6.3 4,3.8, height 7.31
D0008A_L [mm] "SOIC, 8-Leads, Body 4.9x3.9mm, Pitch 1.27mm, IPC High Density"
  oval 1.25x0.55 smd: 1(-2.625,1.905) 2(-2.625,0.635) 3(-2.625,-0.635) 4(-2.625,-1.905) 5(2.625,-1.905) 6(2.625,-0.635) 7(2.625,0.635) 8(2.625,1.905)
  silkscreen extent -3.1,-2.5 0.9,2.5, body extent -3,-2.45 3,2.45, height 1.63
DBZ0003A_N [mm] "SOT23, 3-Leads, Body 2.9x1.3mm, Pitch 0.95mm, Lead Span 2.4mm, IPC Medium Density"
  rrect17% 1x0.6 smd: 1(-1.2,0.95) 2(-1.2,-0.95) 3(1.2,0)
  silkscreen extent 0.2,-1.5 0.7,1.5, body extent -1.26,-1.46 1.26,1.46, height 0.98
DFE252012P [mm] "TOKO, Pad sizes increased as per request"
  rect 0.9x2 smd: 1(-1.05,0) 2(1.05,0)
  silkscreen extent -0.3,-1.2 0.3,1.2, body extent -1.35,-1.1 1.35,1.1, height 1.2
DRB0008B [mm] "SON, 8-Leads, Body 3x3mm, Pitch 0.65mm, Thermal Pad 2.4x1.65mm, TI Recommended"
  rrect33% 0.6x0.3 smd: 1(-1.4,0.975) 2(-1.4,0.325) 3(-1.4,-0.325) 4(-1.4,-0.975) 5(1.4,-0.975) 6(1.4,-0.325) 7(1.4,0.325) 8(1.4,0.975)
  rrect9% 1.47x1.06 on Top Paste: 9(0,-0.63) 9(0,0.63)
  rrect6% 1.65x2.4 smd paste-1.2: 9(0,0)
  silkscreen extent -1.73,-1.73 1.73,1.73, body extent -1.5,-1.5 1.5,1.5, height 0.96
DRL0006A [mm] "SOTFL, 6-Flat Leads, Body 1.2x1.6x0.6mm, Pitch 0.5mm, TI recommended"
  rrect33% 0.67x0.3 smd: 1(-0.74,0.5) 2(-0.74,0) 3(-0.74,-0.5) 4(0.74,-0.5) 5(0.74,0) 6(0.74,0.5)
  silkscreen extent -0.9,-0.95 0.5,0.95, body extent -0.8,-0.8 0.8,0.8, height 0.61
DRY0006A [mm] "USON-6"
  rrect67% 0.45x0.3 smd paste-0.05 mask-0.05: 1(-0.275,0.5)
  rrect67% 0.4x0.3 smd paste-0.05 mask-0.05: 2(-0.3,0) 3(-0.3,-0.5) 4(0.3,-0.5) 5(0.3,0) 6(0.3,0.5)
  body extent -0.5,-0.72 0.5,0.73, height 0.58
ESD_Overlay_Small [mil]
  silkscreen extent -62,-48 64,61
FCC_disclaimer [mil]
FIDUCIAL10-20 [mm]
  round 1 smd mask+0.5: 1(0,0)
  TOP keep-out circle w1.178: c0,0 r0.5
IEC_HotSurface_Small [mil]
  silkscreen extent -107,-93 107,92
JOHNSON_128-0711-201 [mm] "UMC Straight Jack Receptacle, 50 Ohm, SMT"
  rrect10% 1x1.05 smd: 1(0,1.525)
  rrect10% 1.05x2.2 smd: 2(-1.475,0) 3(1.475,0)
  silkscreen extent -0.6,-1.3 0.6,-1.3, body extent -1.5,-1.55 1.5,1.55, height 1.25
Keystone5001 [mil] "For Keystone 500x miniature loop terminals"
  round 80 hole 40: 1(0,0)
  silkscreen extent -52,-52 52,52, body extent -49,-49 49,49, height 182
KYOCERA_CX3225SA [mm] "SMD, 4-Leads, Body 3.2x2.5mm"
  rrect10% 1.05x1.45 smd: 1(-0.925,1.075) 2(-0.925,-1.075) 3(0.925,-1.075) 4(0.925,1.075)
  silkscreen extent -1.78,1.63 -1.65,1.76, body extent -1.3,-1.65 1.3,1.65, height 0.9
Label_650x200 [mil] "Thermal Transfer Label"
  round 1 on Mech13: 0(0,0)
  silkscreen extent -325,-100 325,100, body extent -325,-100 325,100, height 1
"LS L29K_Red" [mm] "SMD, 2-Leads, Body 1.3x0.8mm"
  rect 0.8x0.8 smd paste-0.4: 1(-0.75,0) 2(0.75,0)
  silkscreen extent -0.1,-0.5 1.45,0.5, body extent -0.9,-0.45 0.9,0.45, height 0.67
NDK_NX3225SA [mm] "NDK"
  rect 1.2x1.4 smd: 1(-0.8,1.1) 2(-0.8,-1.1) 3(0.8,-1.1) 4(0.8,1.1)
  body extent -1.3,-1.65 1.3,1.65, height 0.7
NLCV32 [mm] "TDK"
  rect 1.2x2 smd: 1(-1.6,0) 2(1.6,0)
  silkscreen extent -0.9,-1.4 0.9,1.4, body extent -1.7,-1.35 1.7,1.35, height 2.4
ON-SHORE_OSTTE030161 [mm] "Terminal Block, 3.5mm, 3x1, TH"
  rrect50% 1.7x1.7 hole 1.2: 1(-3.5,0)
  round 1.7 hole 1.2: 2(0,0) 3(3.5,0)
  silkscreen extent -5.25,-3.6 5.25,4.05, body extent -5.75,-3.6 5.75,3.4, height 8.4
